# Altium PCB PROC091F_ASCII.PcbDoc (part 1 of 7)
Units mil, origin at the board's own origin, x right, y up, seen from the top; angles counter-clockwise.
Board outline 3590.95 x 906.17 mil, 8 copper layers (Top Layer, GND1, Sig1, PWR1, PWR2, Sig2, GND2, Bottom Layer), stack 63.146 mil thick; 420 components, 316 nets, 1432 pads, 774 vias.
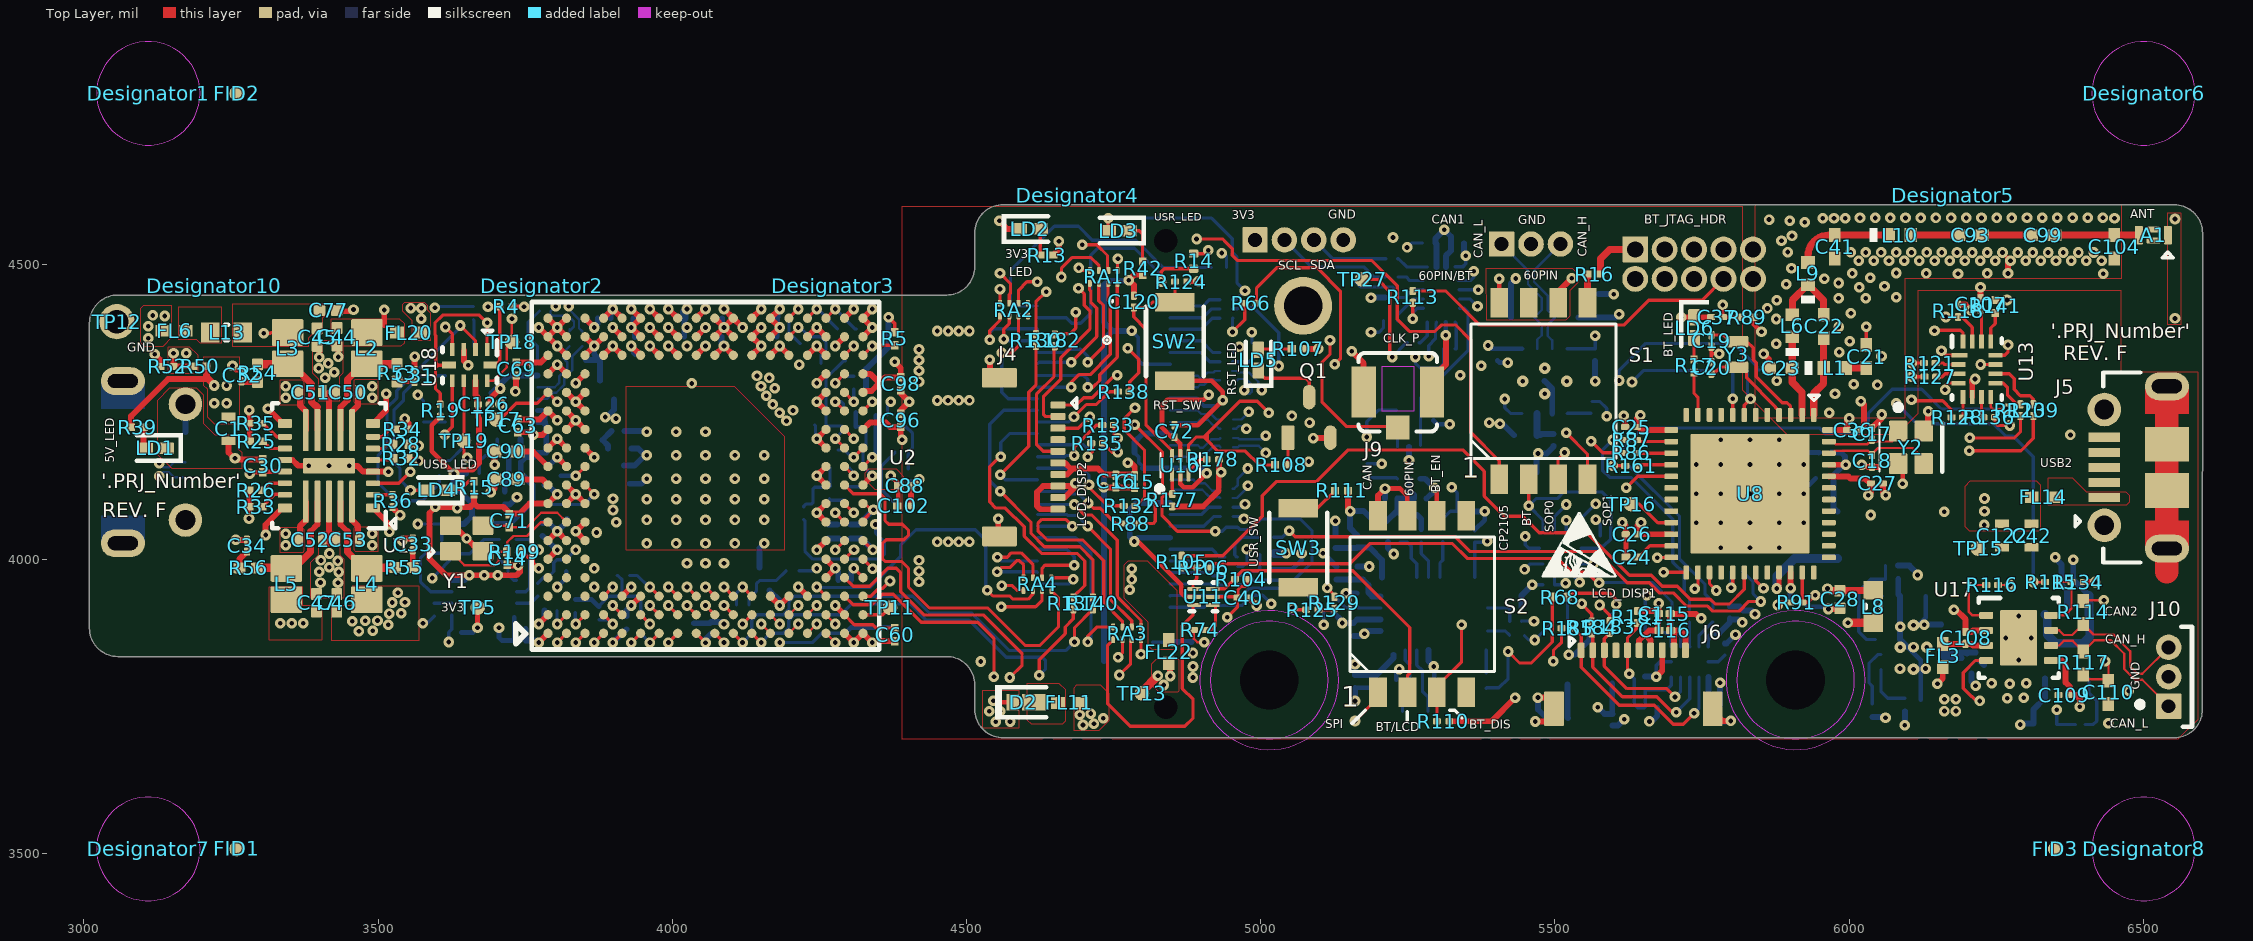
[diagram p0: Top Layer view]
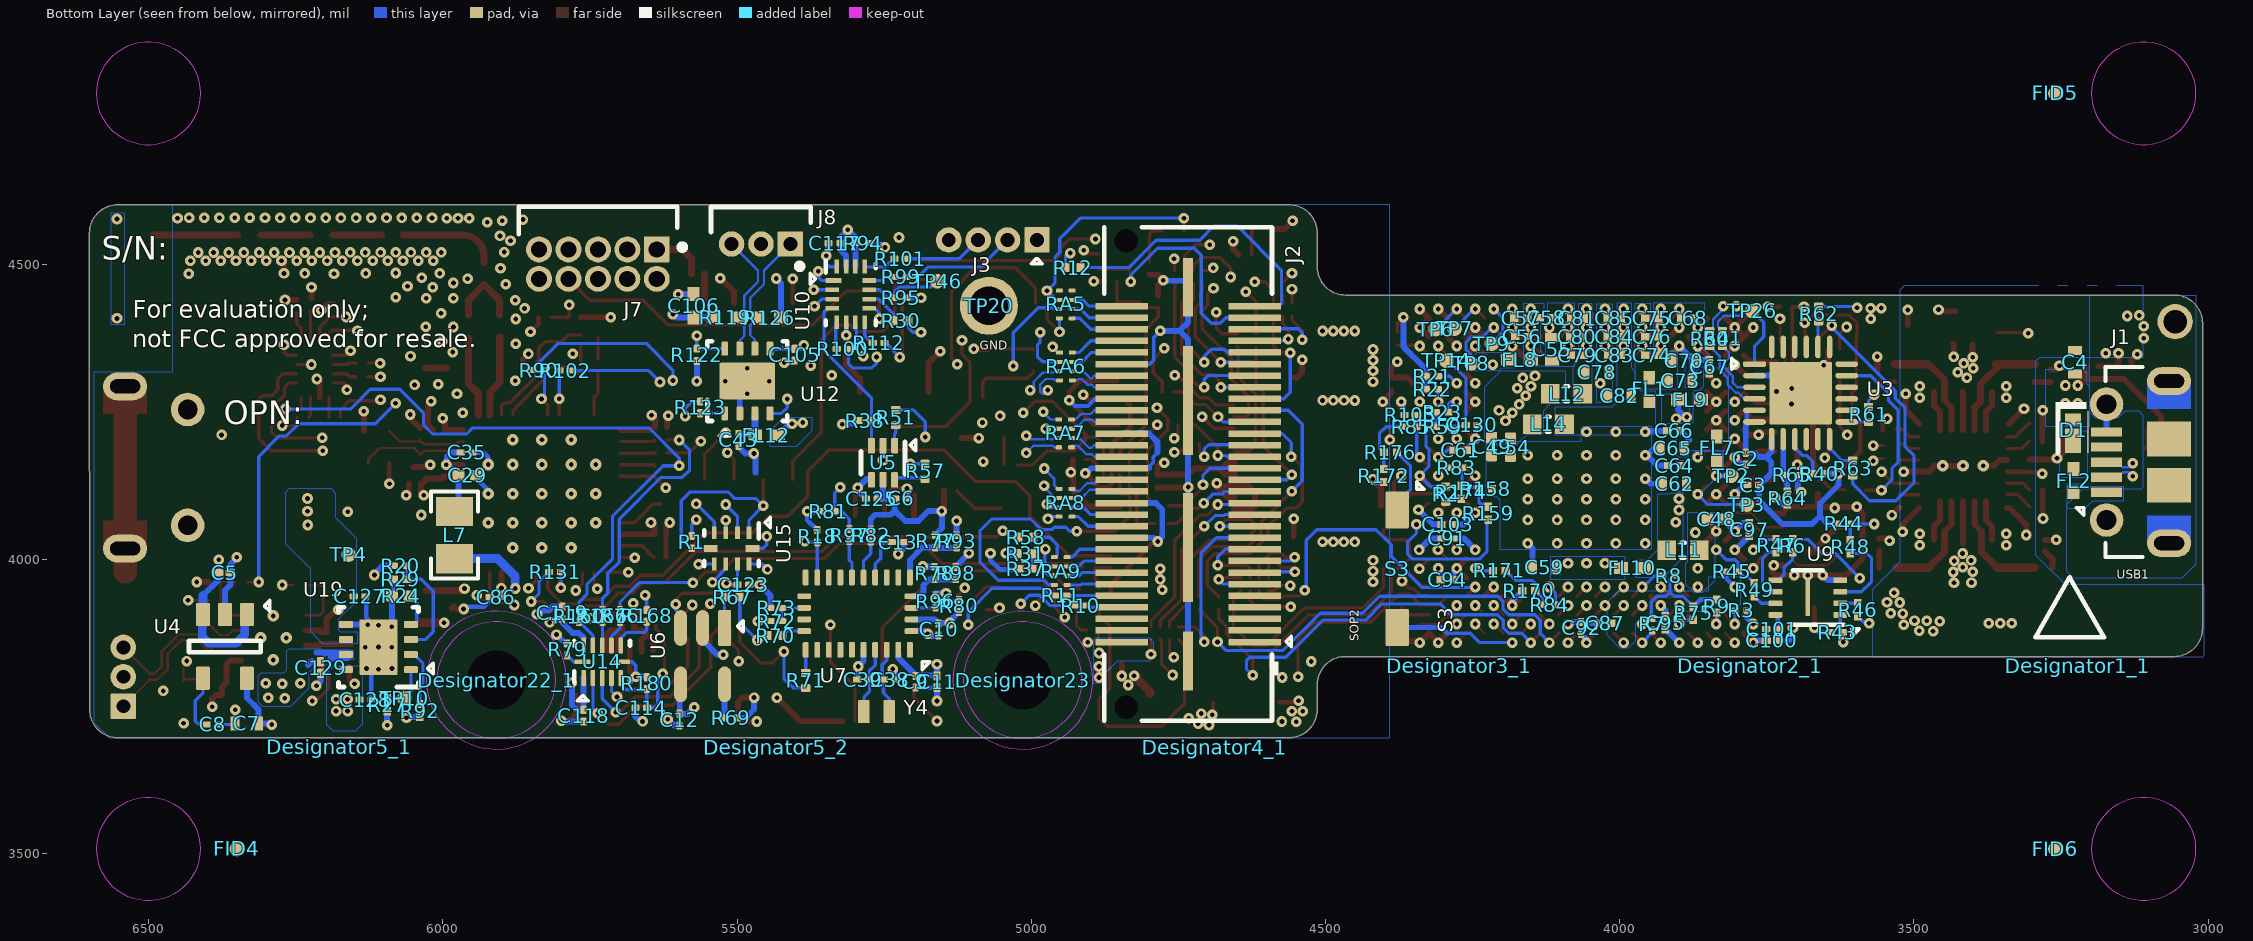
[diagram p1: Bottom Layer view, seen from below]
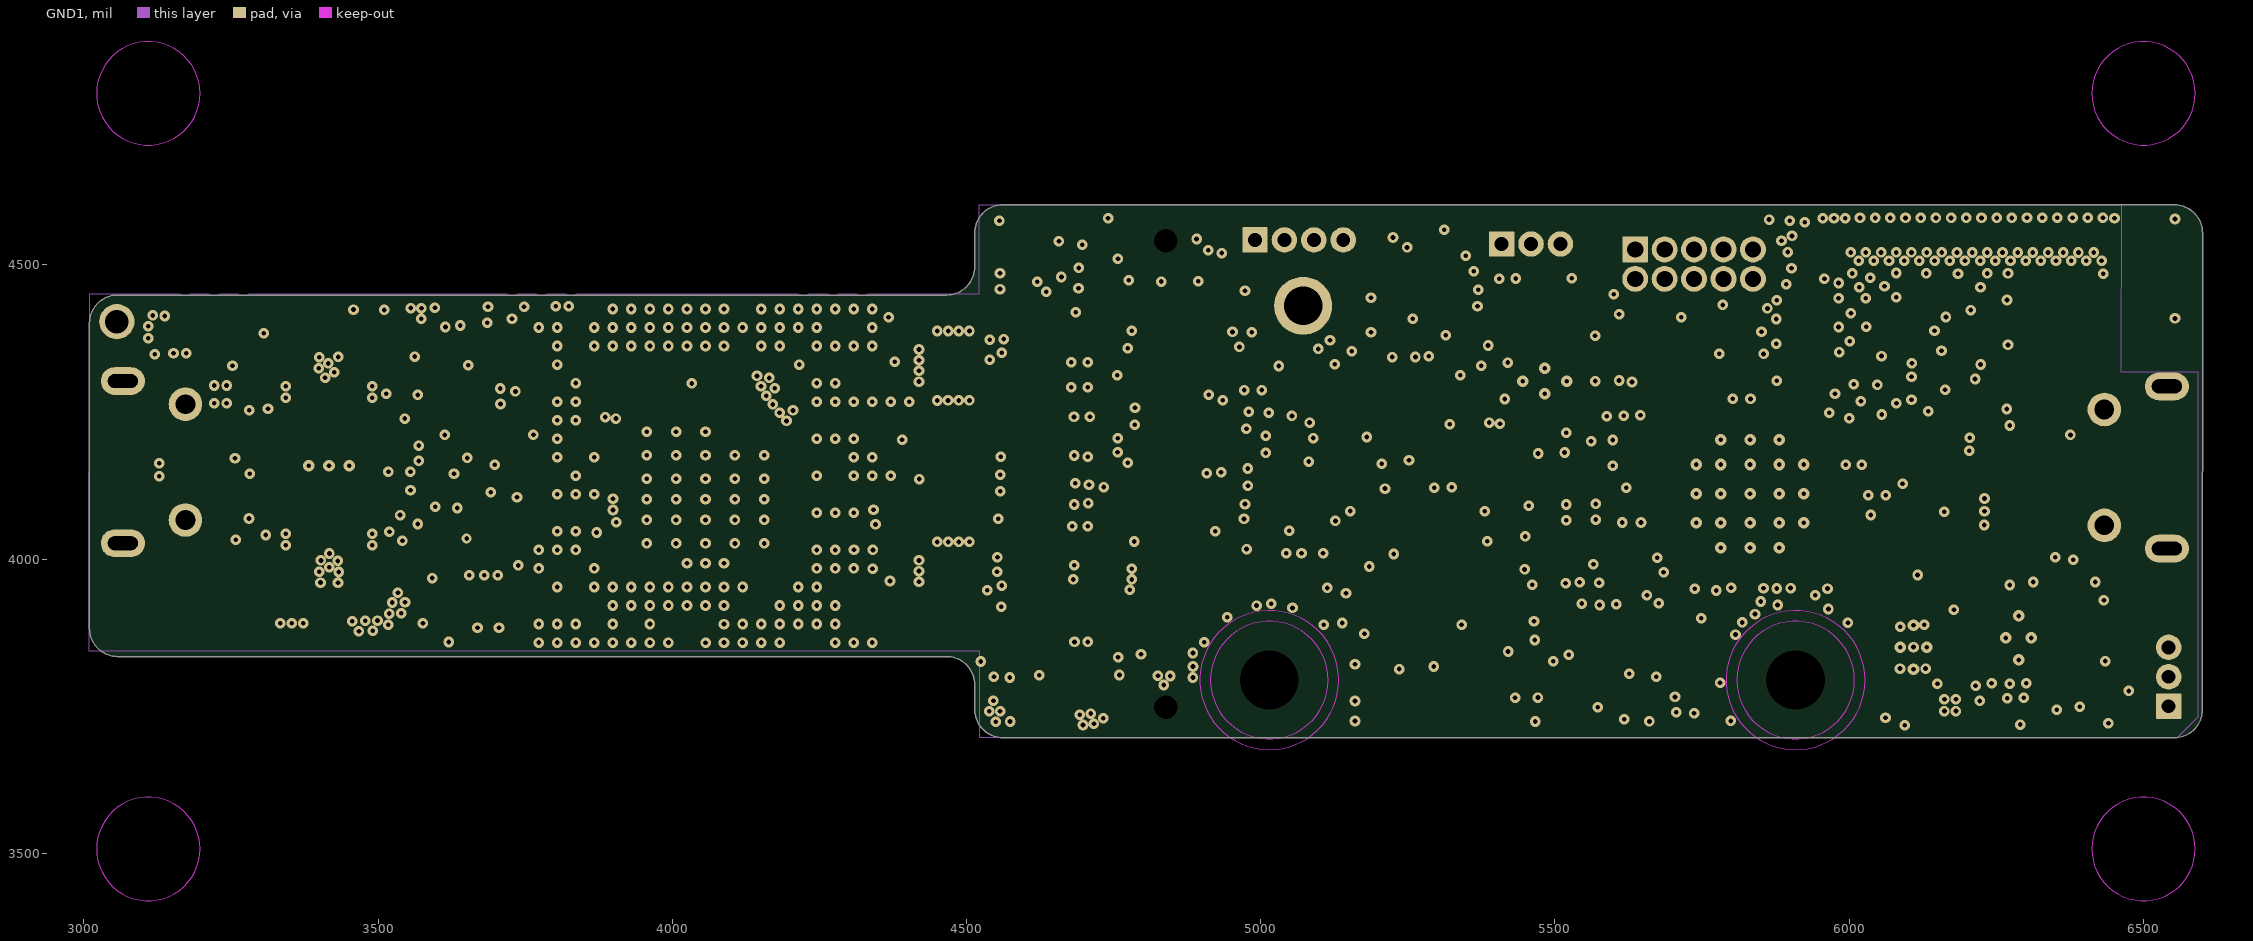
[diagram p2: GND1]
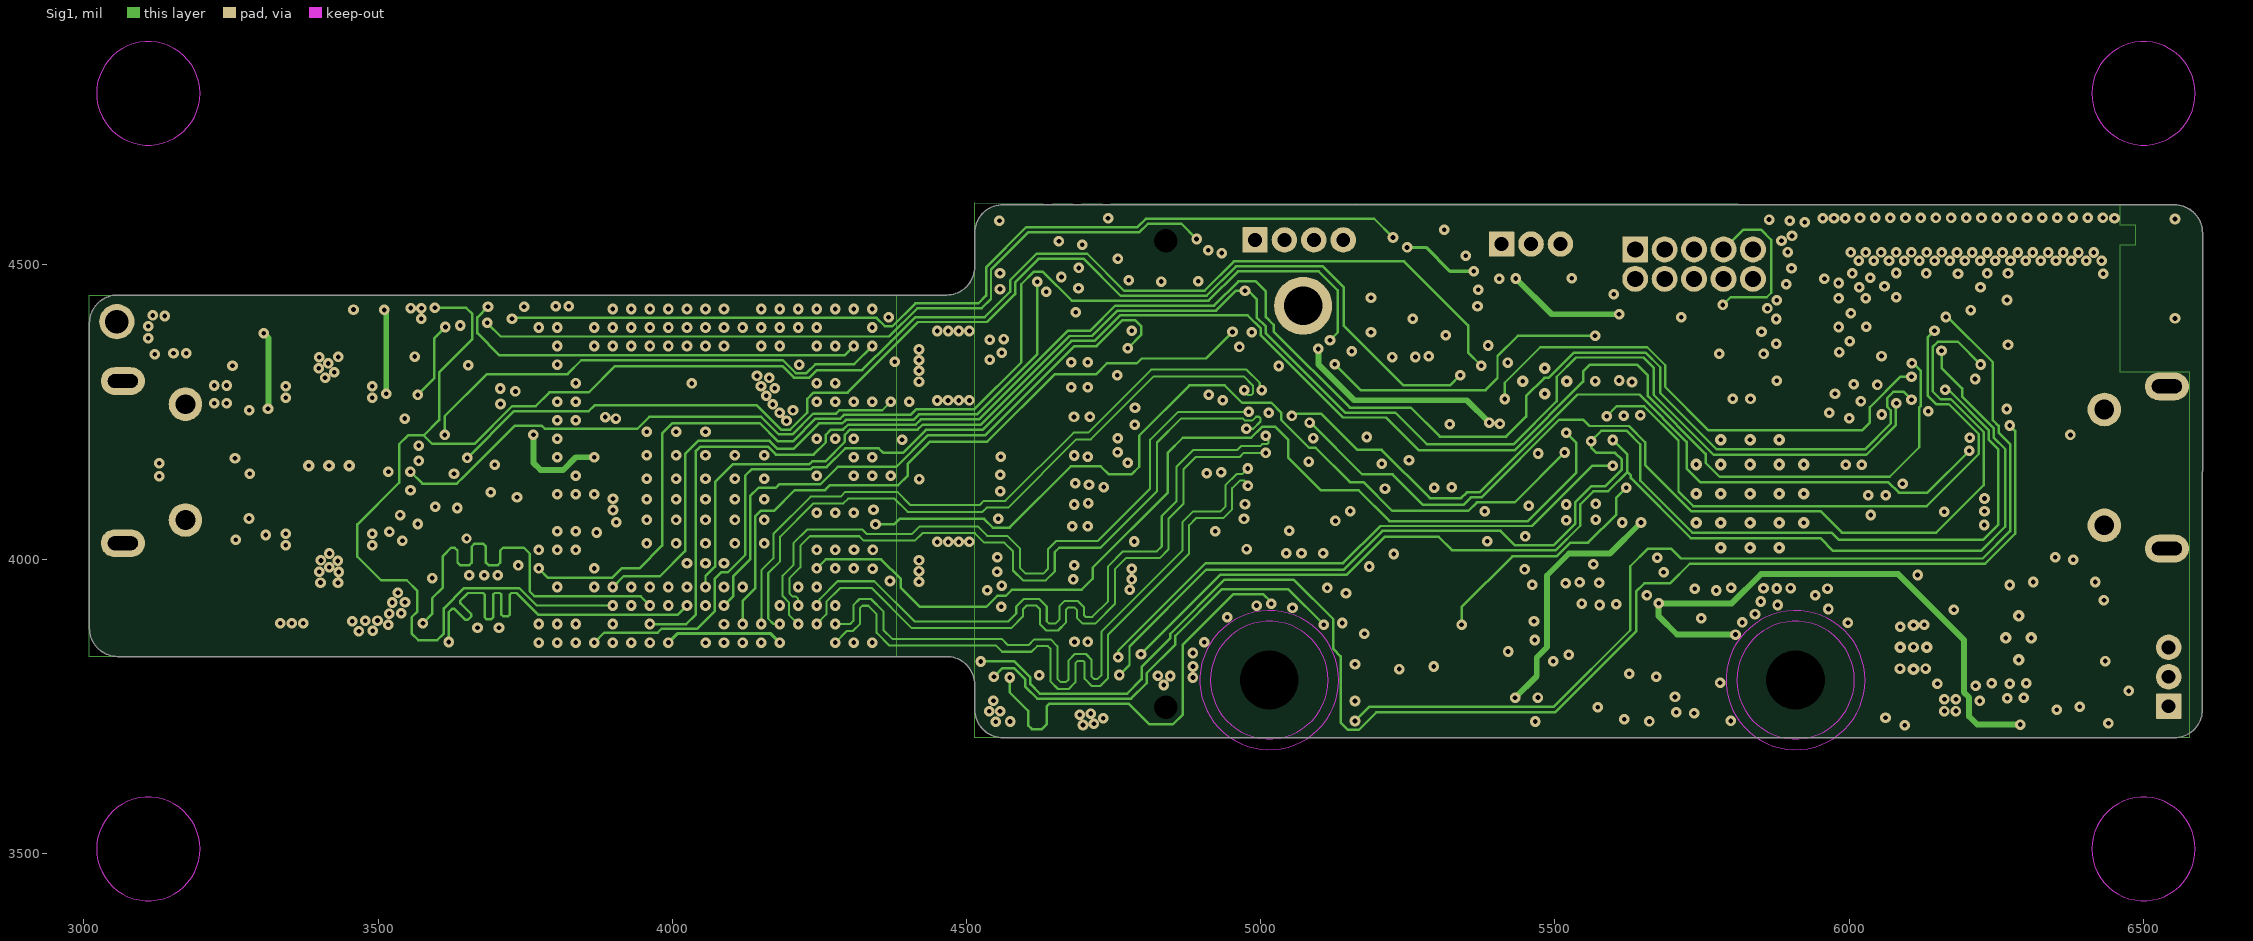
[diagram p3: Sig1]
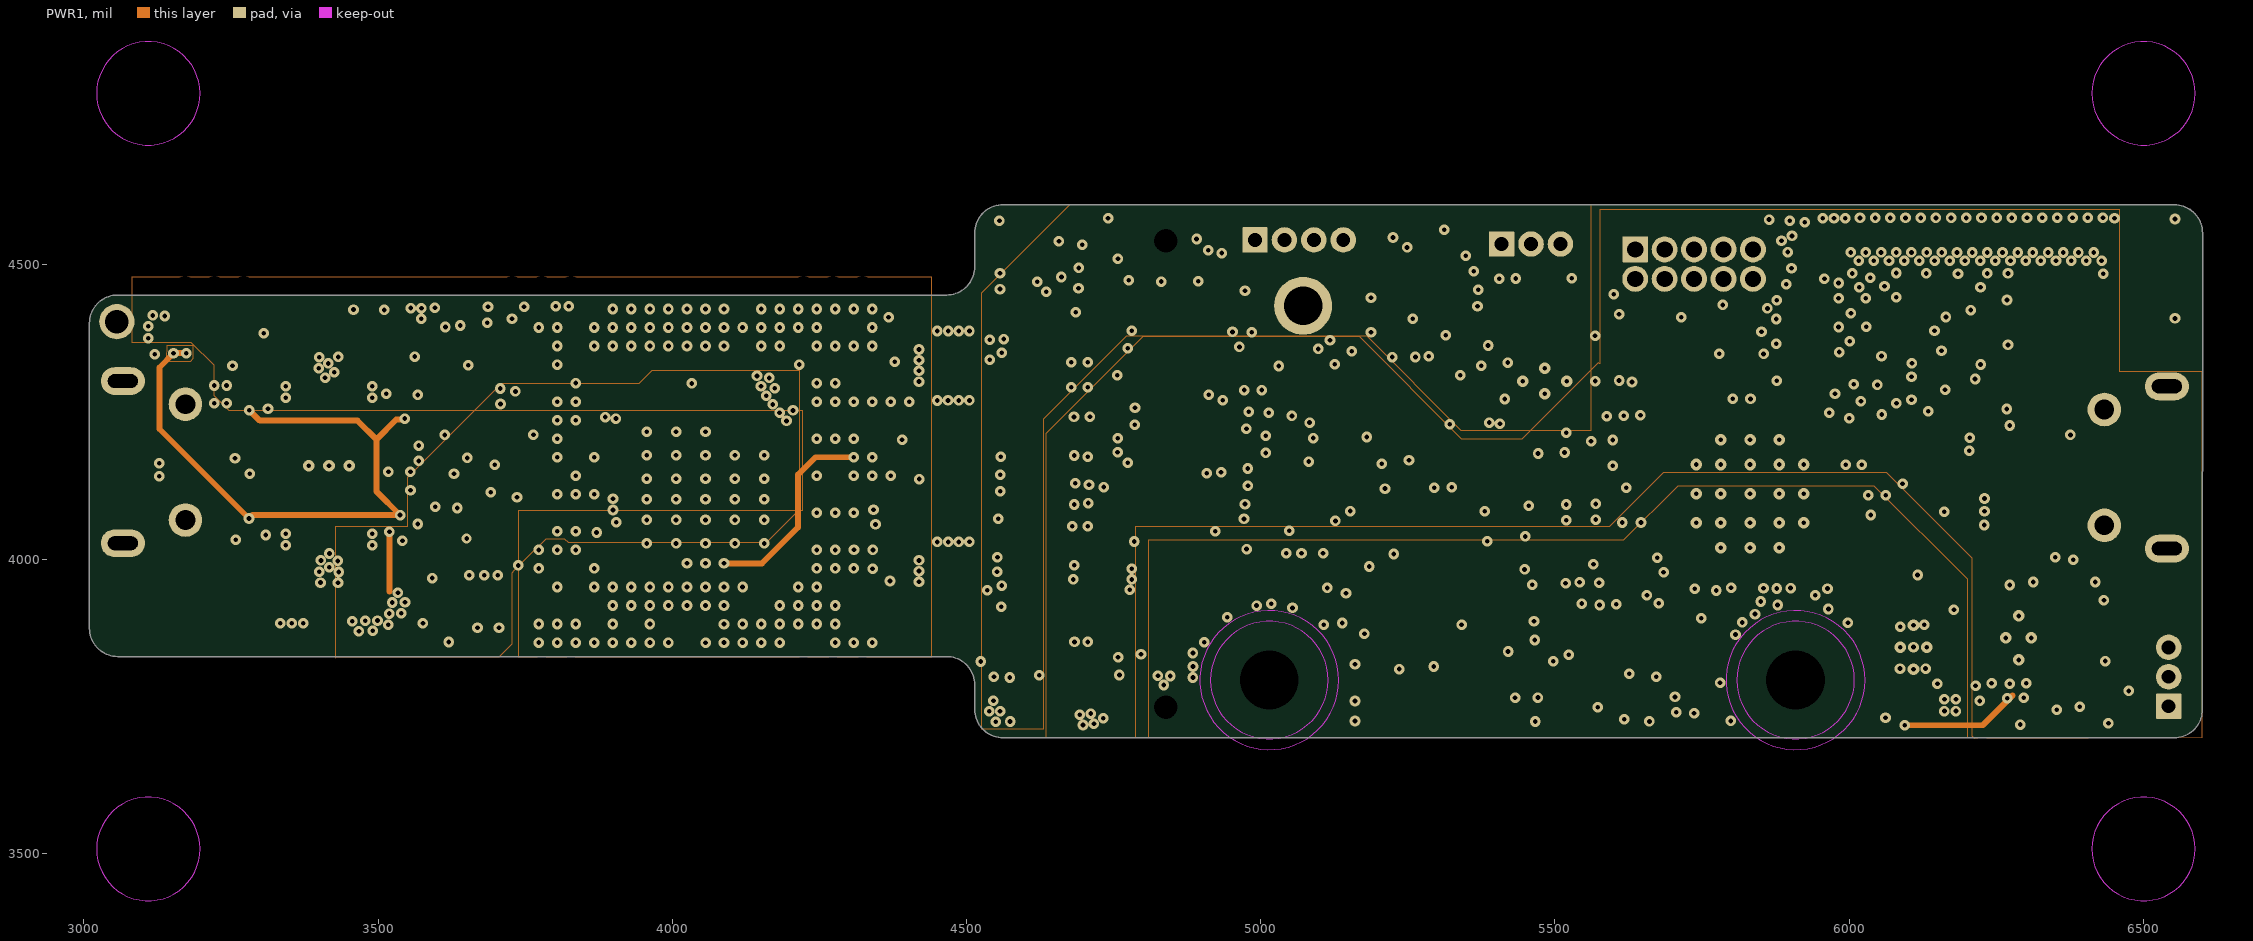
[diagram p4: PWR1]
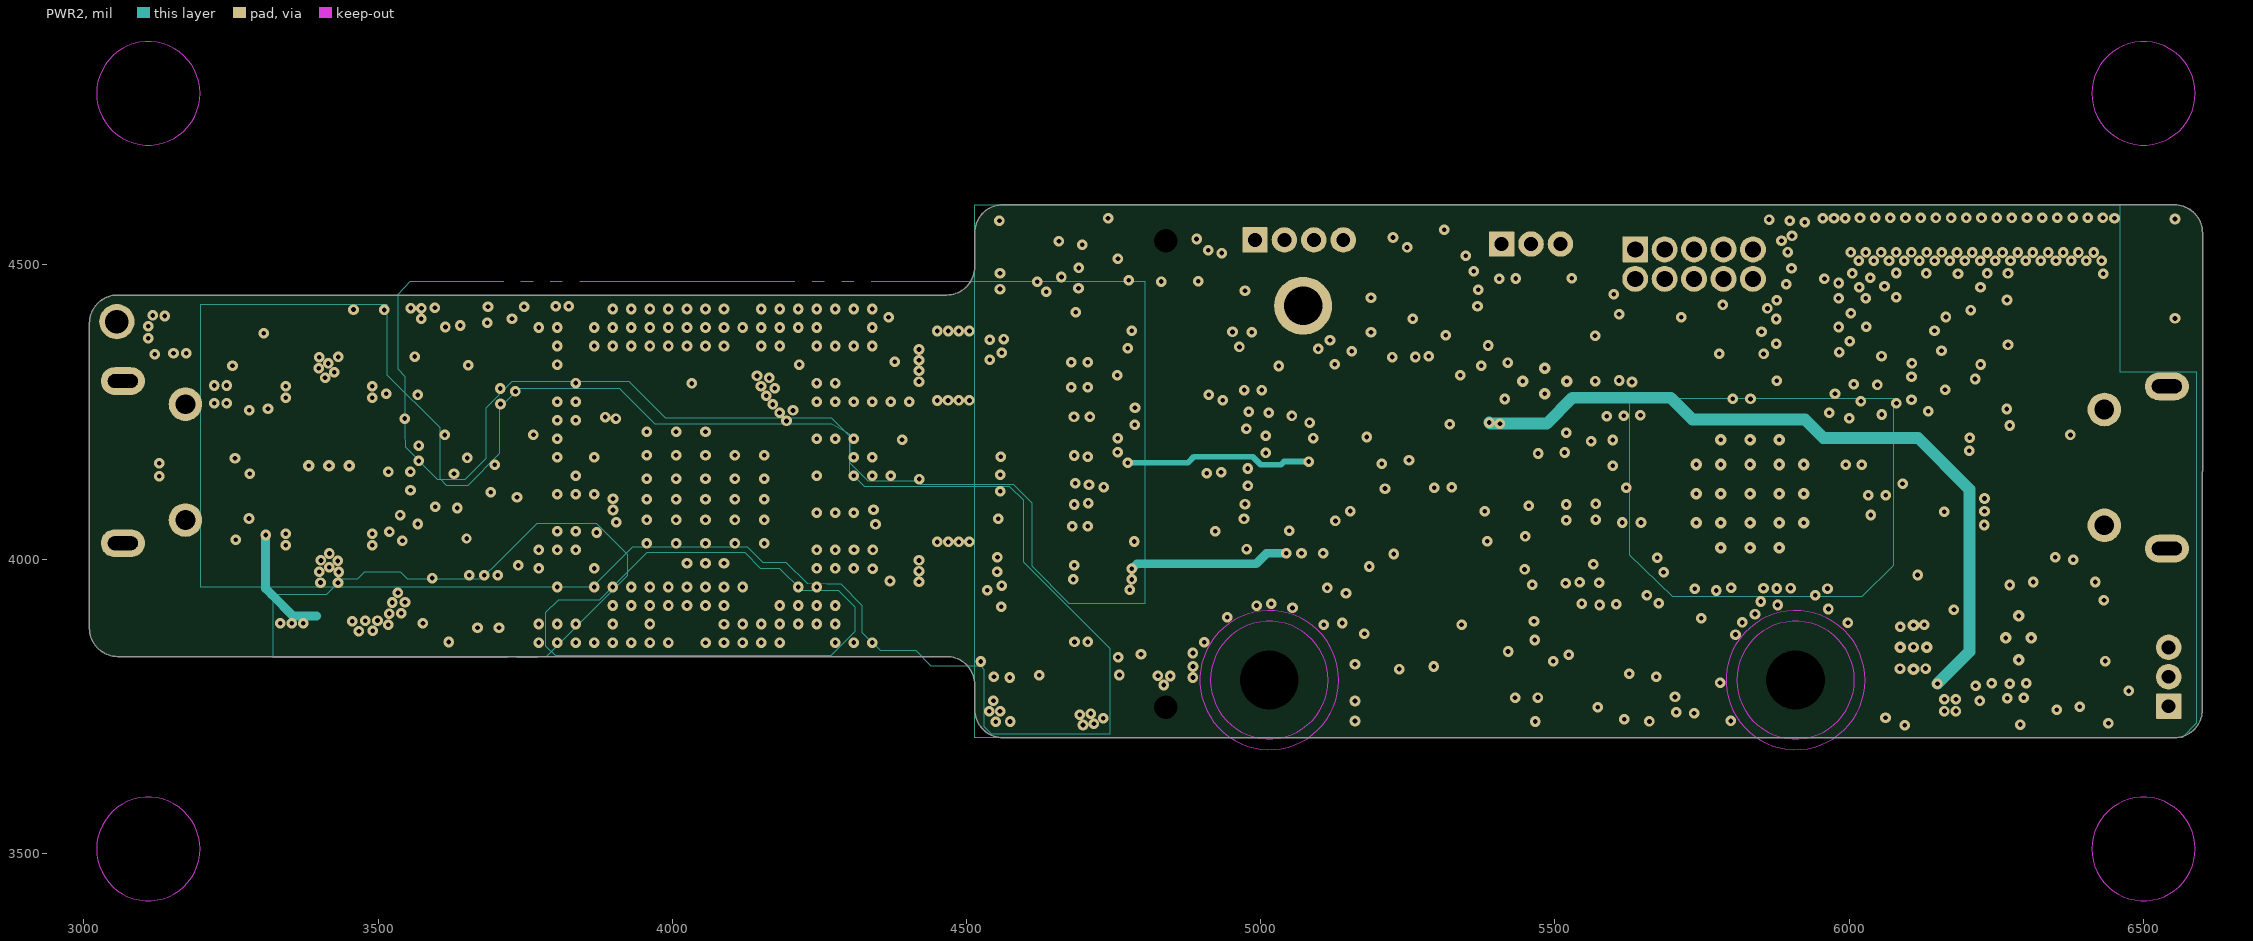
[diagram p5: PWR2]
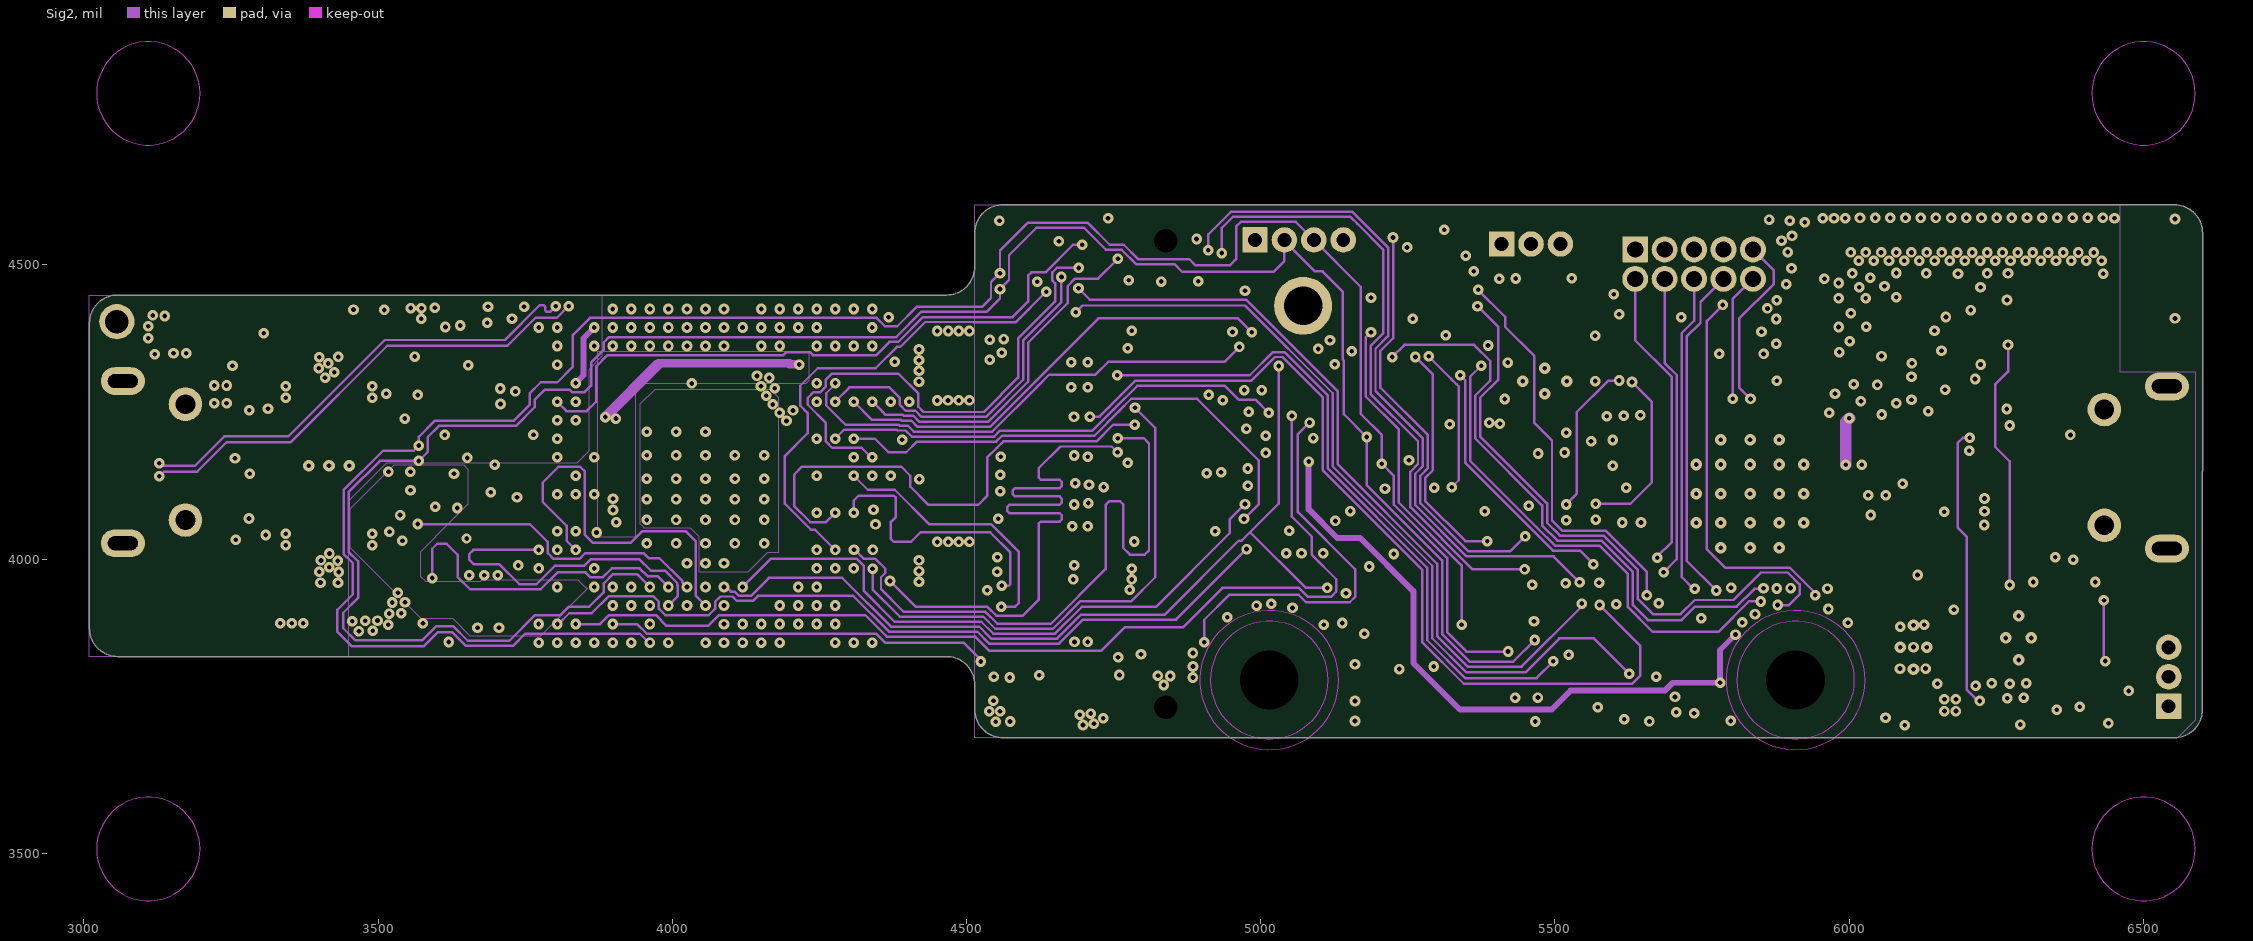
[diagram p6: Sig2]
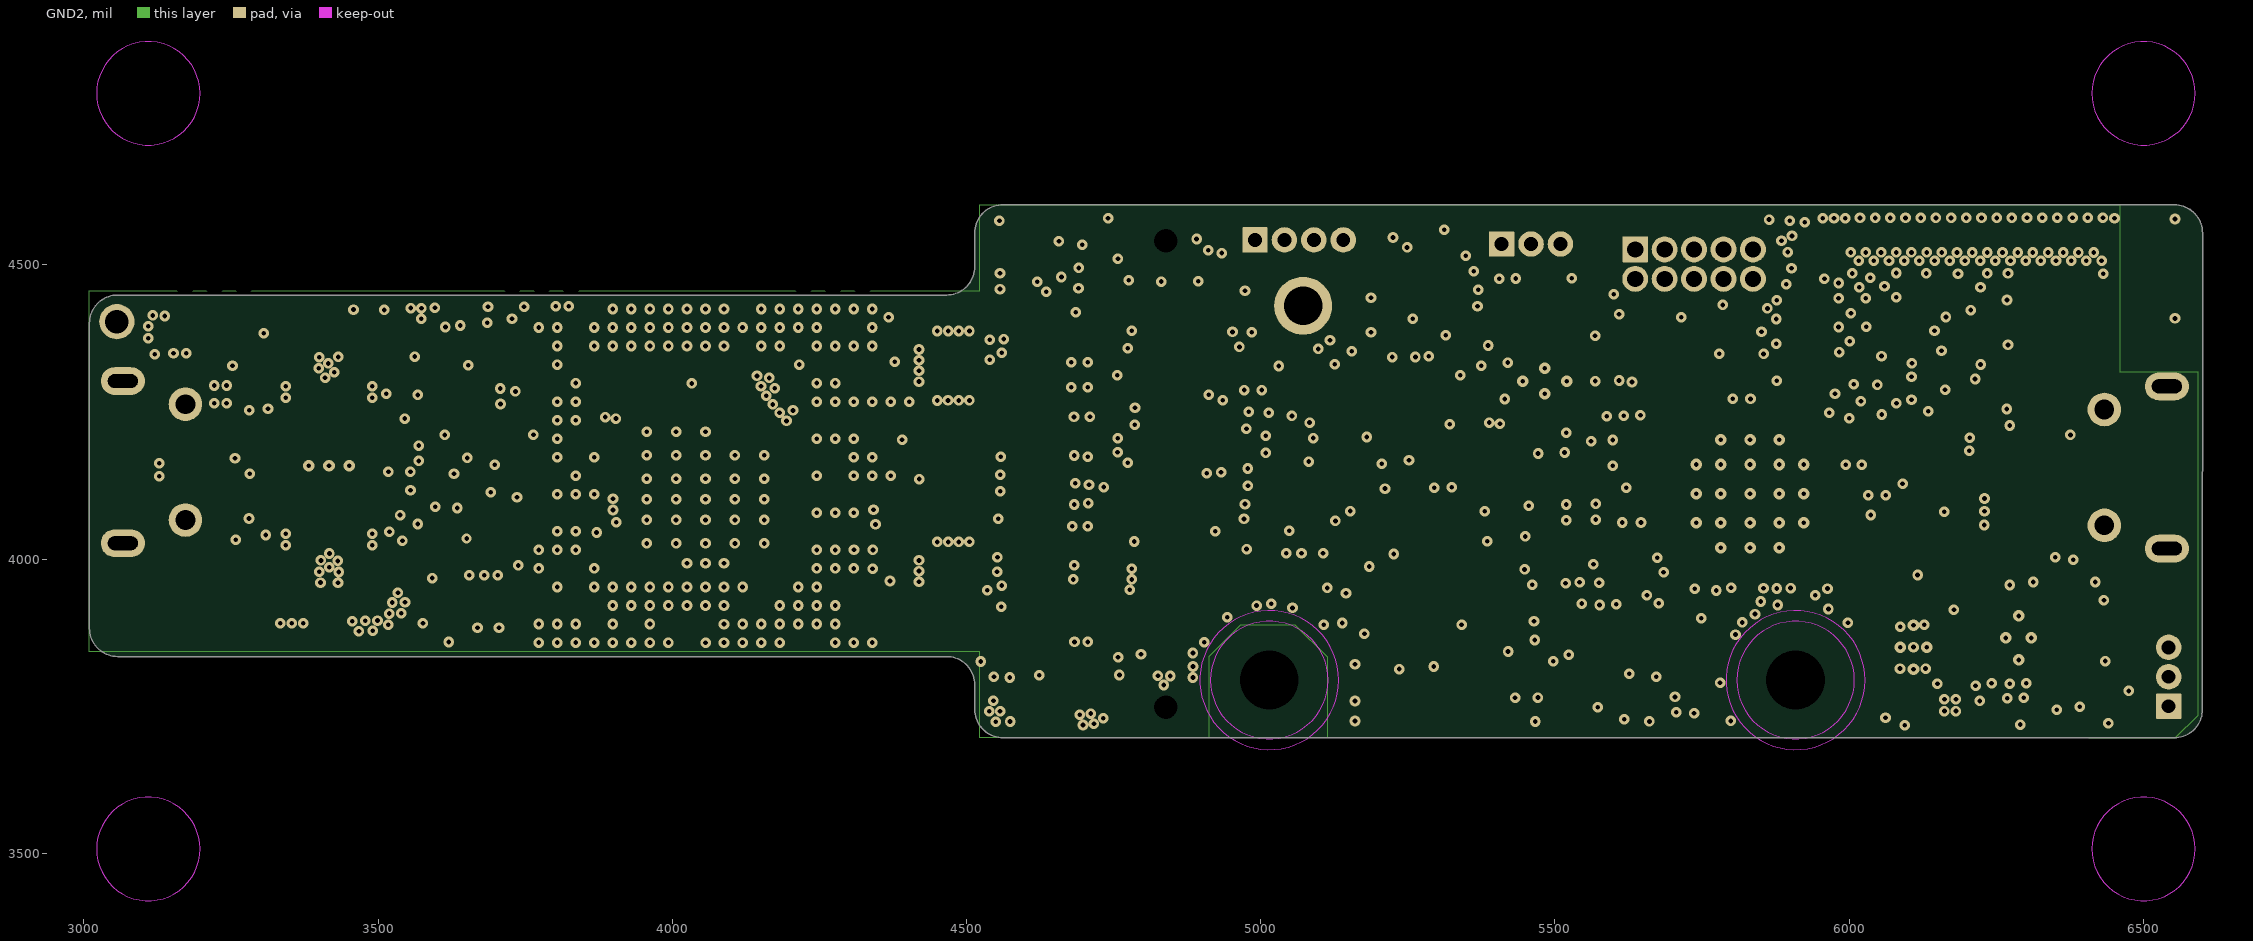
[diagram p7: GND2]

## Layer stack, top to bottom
Top Solder: solder mask 0.5, Solder Resist, Dk 3.5
Top Layer: signal copper 1.373
Dielectric1: core 3.7, FR-4 High Tg, Dk 4.2
GND1: signal copper 2.4
Dielectric3: dielectric 4.5, FR-4 High Tg, Dk 4.2
Sig1: signal copper 1.2
Dielectric2: dielectric 12, FR-4 High Tg, Dk 4.2
PWR1: signal copper 2.4
Dielectric4: dielectric 8, FR-4 High Tg, Dk 4.2
PWR2: signal copper 2.4
Dielectric5: dielectric 12, FR-4 High Tg, Dk 4.2
Sig2: signal copper 1.2
Dielectric8: dielectric 4.5, FR-4 High Tg, Dk 4.2
GND2: signal copper 2.4
Dielectric9: dielectric 3.7, FR-4 High Tg, Dk 4.2
Bottom Layer: signal copper 1.373
Bottom Solder: solder mask 0.5, Solder Resist, Dk 3.5

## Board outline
3057.58,3834.46 4466.14,3834.46 cw(c4466.14,3786.46) 4514.14,3786.46 4514.14,3744.46 ccw(c4562.14,3744.46) 4562.14,3696.46 4562.14,3696.51 6552.27,3696.2 ccw(c6552.27,3744.2) 6600.27,3744.2 6600.29,3744.2 6600.53,4554.1 ccw(c6552.53,4554.1) 6552.53,4602.1 6552.53,4602.08 4562.15,4602.33 4562.15,4602.37 ccw(c4562.15,4554.37) 4514.15,4554.37 4514.15,4496.76 cw(c4466.15,4496.76) 4466.15,4448.76 3057.58,4448.76 ccw(c3057.58,4400.76) 3009.58,4400.76 3009.58,3882.46 ccw(c3057.58,3882.46)

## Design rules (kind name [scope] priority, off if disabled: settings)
AcuteAngle [All] p0: scope1count=1 scope1_0_kind=Board scope1_0_value=Board scope2count=1 scope2_0_kind=Board scope2_0_value=Board commentlength=0 minimum=4.50000000000000E+0001
AcuteAngle [All] p1: minimum=4.50000000000000E+0001 checktracksonly=TRUE
AssemblyTestPointUsage [All] p0: scope1count=1 scope1_0_kind=Board scope1_0_value=Board scope2count=1 scope2_0_kind=Board scope2_0_value=Board commentlength=0
AssemblyTestPointUsage [All] p1: valid=2
AssemblyTestpoint [All] p0: scope1count=1 scope1_0_kind=Board scope1_0_value=Board scope2count=1 scope2_0_kind=Board scope2_0_value=Board commentlength=0
BoardOutlineClearance [All] p0 off: scope1count=1 scope1_0_kind=Board scope1_0_value=Board scope2count=1 scope2_0_kind=Board scope2_0_value=Board commentlength=81 gap=12 // Protel DXP Scope 1 Expression Was: NOT(OnTopSilkscreen OR OnBottomSilkscreen)
BoardOutlineClearance BoardOutlineClearance_1 [All] p0: scope1count=1 scope1_0_kind=Net scope1_0_value=GND scope2count=1 scope2_0_kind=Board scope2_0_value=Board commentlength=0 gap=8
BoardOutlineClearance BoardOutlineClearance_1 [InNet('GND')] p1: gap=8 ignorepadtopadclearanceinfootprint=FALSE
BoardOutlineClearance [NOT(OnTopSilkscreen OR OnBottomSilkscreen)] p2: gap=12 ignorepadtopadclearanceinfootprint=FALSE except(0: Text-OutlineEdge)
Clearance INNERlayer [All] p0 off: scope1count=1 scope1_0_kind=Board scope1_0_value=Board scope2count=1 scope2_0_kind=Board scope2_0_value=Board commentlength=75 gap=8 // Protel DXP Scope 1 Expression Was: (OnLayer('pwr1') or OnLayer('pwr2'))
Clearance "SAME NET" [All] p0: scope1count=1 scope1_0_kind=Board scope1_0_value=Board scope2count=1 scope2_0_kind=Board scope2_0_value=Board commentlength=0 gap=0
Clearance [All] p0: scope1count=1 scope1_0_kind=Board scope1_0_value=Board scope2count=1 scope2_0_kind=Board scope2_0_value=Board commentlength=0 gap=1
Clearance 50E_INNERlayer [All] p0 off: scope1count=1 scope1_0_kind=Board scope1_0_value=Board scope2count=1 scope2_0_kind=Board scope2_0_value=Board commentlength=75 gap=4.2 // Protel DXP Scope 1 Expression Was: (OnLayer('sig1') or OnLayer('Sig2'))
Clearance 100E [All] p0 off: scope1count=1 scope1_0_kind=Board scope1_0_value=Board scope2count=1 scope2_0_kind=Board scope2_0_value=Board commentlength=70 gap=8 // Protel DXP Scope 1 Expression Was: InDifferentialPairClass('100E')
Clearance AOP_Sig [All] p0 off: scope1count=1 scope1_0_kind=Board scope1_0_value=Board scope2count=1 scope2_0_kind=Board scope2_0_value=Board commentlength=97 gap=4 // Protel DXP Scope 1 Expression Was: WithinRoom('BGA') AND (OnLayer('sig1') or OnLayer('sig2'))
Clearance AOP_T-B [All] p0 off: scope1count=1 scope1_0_kind=Board scope1_0_value=Board scope2count=1 scope2_0_kind=Board scope2_0_value=Board commentlength=48 gap=4 // Protel DXP Scope 2 Expression Was: OnOutside
Clearance 90E_OUTSIDE [All] p0 off: scope1count=1 scope1_0_kind=Board scope1_0_value=Board scope2count=1 scope2_0_kind=Board scope2_0_value=Board commentlength=48 gap=6 // Protel DXP Scope 2 Expression Was: OnOutside
Clearance RF_TRACE [All] p0: scope1count=1 scope1_0_kind=NetClass scope1_0_value=RF scope2count=1 scope2_0_kind=Board scope2_0_value=Board commentlength=0 gap=4
Clearance Keepout [All] p0 off: scope1count=1 scope1_0_kind=Board scope1_0_value=Board scope2count=1 scope2_0_kind=Board scope2_0_value=Board commentlength=66 gap=0.01 // Protel DXP Scope 1 Expression Was: (OnLayer('Keep-Out Layer'))
Clearance Keepout [(OnLayer('Keep-Out Layer'))] p1: gap=0.01 ignorepadtopadclearanceinfootprint=FALSE except(5.9: THPad-THPad; 7: Arc-THPad Track-THPad THPad-Via; 8: THPad-Fill THPad-Poly THPad-Region)
Clearance RF_TRACE [InNetClass('RF')] p2: gap=4 ignorepadtopadclearanceinfootprint=FALSE except(0: Arc-Hole Track-Hole SMDPad-Hole THPad-Hole Via-Hole Fill-Hole Poly-Hole Region-Hole Text-Hole; 2: Arc-Text Track-Text SMDPad-Text THPad-Text Via-Text Fill-Text Poly-Text Region-Text Text-Text; 5.9: THPad-THPad; 6: SMDPad-Fill SMDPad-Poly SMDPad-Region Via-Fill Via-Poly Via-Region; 7: Arc-THPad Track-THPad THPad-Via; 8: THPad-Fill THPad-Poly THPad-Region; 10: Arc-Fill Arc-Poly Arc-Region Track-Fill Track-Poly Track-Region; 15: Fill-Fill Fill-Poly Fill-Region Poly-Poly Poly-Region Region-Region)
Clearance AOP_T-B [WithinRoom('BGA') vs OnOutside] p3: gap=4 ignorepadtopadclearanceinfootprint=TRUE except(0: Arc-Hole Track-Hole SMDPad-Hole THPad-Hole Via-Hole Fill-Hole Poly-Hole Region-Hole Text-Hole; 3.8: SMDPad-Via; 3.9: Arc-Via Track-Via; 5.9: THPad-THPad; 7: Arc-THPad Track-THPad THPad-Via; 8: THPad-Fill THPad-Poly THPad-Region Fill-Fill Fill-Poly Fill-Region Poly-Poly Poly-Region Region-Region)
Clearance AOP_Sig [WithinRoom('BGA') AND (OnLayer('sig1') or OnLayer('sig2'))] p4: gap=4 ignorepadtopadclearanceinfootprint=FALSE except(0: Arc-Hole Track-Hole SMDPad-Hole THPad-Hole Via-Hole Fill-Hole Poly-Hole Region-Hole Text-Hole; 3.5: Arc-Arc Arc-Track Arc-Via Arc-Text Track-Track Track-Via Track-Text SMDPad-Text THPad-Text Via-Via Via-Text Fill-Text Poly-Text Region-Text Text-Text; 3.8: SMDPad-Via; 5.9: THPad-THPad; 7: Arc-THPad Track-THPad THPad-Via; 8: SMDPad-THPad THPad-Fill THPad-Poly THPad-Region; 15: Fill-Fill Fill-Poly Fill-Region Poly-Poly Poly-Region Region-Region)
Clearance 50E_INNERlayer [(OnLayer('sig1') or OnLayer('Sig2'))] p5: gap=4.2 ignorepadtopadclearanceinfootprint=TRUE except(0: Arc-Hole Track-Hole SMDPad-Hole THPad-Hole Via-Hole Fill-Hole Poly-Hole Region-Hole Text-Hole; 2: SMDPad-Text Fill-Text Poly-Text Region-Text Text-Text; 5.9: THPad-THPad; 6: SMDPad-Fill SMDPad-Poly SMDPad-Region; 7: Arc-THPad Track-THPad THPad-Via; 8: Arc-Fill Arc-Poly Arc-Region Track-Fill Track-Poly Track-Region THPad-Fill THPad-Poly THPad-Region; 12: Fill-Fill Fill-Poly Fill-Region Poly-Poly Poly-Region Region-Region)
Clearance INNERlayer [(OnLayer('pwr1') or OnLayer('pwr2'))] p6: gap=8 ignorepadtopadclearanceinfootprint=TRUE except(0: Arc-Hole Track-Hole SMDPad-Hole THPad-Hole Via-Hole Fill-Hole Poly-Hole Region-Hole Text-Hole; 2: SMDPad-Text Fill-Text Poly-Text Region-Text Text-Text; 4: Via-Fill Via-Poly Via-Region; 4.2: Arc-Text Track-Text THPad-Text Via-Via Via-Text; 5: THPad-Fill THPad-Poly THPad-Region; 5.9: THPad-THPad; 6: Arc-Via Arc-Fill Arc-Poly Arc-Region Track-Via Track-Fill Track-Poly Track-Region; 7: THPad-Via; 12: Fill-Fill Fill-Poly Fill-Region Poly-Poly Poly-Region Region-Region)
Clearance 100E [InDifferentialPairClass('100E')] p7: gap=8 ignorepadtopadclearanceinfootprint=FALSE except(0: Arc-Hole Track-Hole SMDPad-Hole THPad-Hole Via-Hole Fill-Hole Poly-Hole Region-Hole Text-Hole; 2: Arc-Text Track-Text THPad-Text Via-Text Fill-Text Poly-Text Region-Text Text-Text; 4: Arc-SMDPad Track-SMDPad SMDPad-SMDPad SMDPad-THPad SMDPad-Via SMDPad-Text Via-Via Via-Fill Via-Poly Via-Region; 5: Arc-Via Track-Via; 5.9: THPad-THPad; 6: SMDPad-Fill SMDPad-Poly SMDPad-Region Fill-Fill Fill-Poly Fill-Region Poly-Poly Poly-Region Region-Region; 7: Arc-THPad Track-THPad THPad-Via)
Clearance 90E_OUTSIDE [InDifferentialPairClass('90E') vs OnOutside] p8: gap=6 ignorepadtopadclearanceinfootprint=TRUE except(0: Arc-Hole Track-Hole SMDPad-Hole THPad-Hole Via-Hole Fill-Fill Fill-Poly Fill-Region Fill-Hole Poly-Poly Poly-Region Poly-Hole Region-Region Region-Hole Text-Hole; 2: Arc-Text Track-Text SMDPad-Text THPad-Text Via-Text Fill-Text Poly-Text Region-Text Text-Text; 3.8: SMDPad-Via; 4: Arc-SMDPad Track-SMDPad SMDPad-SMDPad Via-Via Via-Fill Via-Poly Via-Region; 4.5: Arc-Arc Arc-Track Arc-Via Track-Track Track-Via; 5.9: THPad-THPad; 7: Arc-THPad Track-THPad SMDPad-THPad THPad-Via; 8: THPad-Fill THPad-Poly THPad-Region)
Clearance [All] p9: gap=1 ignorepadtopadclearanceinfootprint=TRUE except(0: Arc-Hole Track-Hole SMDPad-Hole THPad-Hole Via-Hole Fill-Hole Poly-Hole Region-Hole Text-Hole; 4: SMDPad-SMDPad SMDPad-Via Via-Via Via-Fill Via-Poly Via-Region; 5: Arc-SMDPad Arc-Fill Arc-Poly Arc-Region Track-SMDPad Track-Fill Track-Poly Track-Region; 5.9: THPad-THPad; 6: Arc-Arc Arc-Track Arc-Via Track-Track Track-Via SMDPad-Fill SMDPad-Poly SMDPad-Region; 7: Arc-THPad Track-THPad SMDPad-THPad THPad-Via; 8: THPad-Fill THPad-Poly THPad-Region; 12: Fill-Fill Fill-Poly Fill-Region Poly-Poly Poly-Region Region-Region)
Clearance "SAME NET" [All] p10: gap=0 ignorepadtopadclearanceinfootprint=FALSE except(0.5: SMDPad-Text; 5.9: THPad-THPad)
ComponentClearance ComponentClearance_THtoTH [All] p0 off: scope1count=1 scope1_0_kind=Board scope1_0_value=Board scope2count=1 scope2_0_kind=Board scope2_0_value=Board commentlength=54 gap=20 collisioncheckmode=3 // Protel DXP Scope 2 Expression Was: IsThruComponent
ComponentClearance ComponentClearance_THtoSMT [All] p0 off: scope1count=1 scope1_0_kind=Board scope1_0_value=Board scope2count=1 scope2_0_kind=Board scope2_0_value=Board commentlength=53 gap=5 collisioncheckmode=3 // Protel DXP Scope 2 Expression Was: IsSMTComponent
ComponentClearance ComponentClearance_SmallPassives [All] p0 off: scope1count=1 scope1_0_kind=Board scope1_0_value=Board scope2count=1 scope2_0_kind=Board scope2_0_value=Board commentlength=508 gap=10 collisioncheckmode=3 // Protel DXP Scope 2 Expression Was: HasFootprint('0201*') or HasFootprint('0402*') or HasFootprint('0508') or HasFootprint('0603*') or HasFootprint('0612') or HasFootprint('0805*') or HasFootprint('0815*') or HasFootprint('0830*') or HasFootprint('1206*') or HasFootprint('1210*') or HasFootprint('1808*') or HasFootprint('1812*') or HasFootprint('1825*') or HasFootprint('2010*') or HasFootprint('2220*') or HasFootprint('2225*') or HasFootprint('2512*') or HasFootprint('2728*') or HasFootprint('3518*')
ComponentClearance ComponentClearance_MountingHoles [All] p0: scope1count=1 scope1_0_kind=ComponentClass scope1_0_value="Mounting Holes" scope2count=1 scope2_0_kind=Board scope2_0_value=Board commentlength=0 gap=20 collisioncheckmode=3
ComponentClearance ComponentClearance_ScrewToNut [All] p0 off: scope1count=1 scope1_0_kind=Board scope1_0_value=Board scope2count=1 scope2_0_kind=Board scope2_0_value=Board commentlength=71 gap=5 collisioncheckmode=3 // Protel DXP Scope 2 Expression Was: (HasFootprint('Keystone_1902C'))
ComponentClearance ComponentClearance_Logo [All] p0: scope1count=1 scope1_0_kind=ComponentClass scope1_0_value=Logo scope2count=1 scope2_0_kind=Board scope2_0_value=Board commentlength=0 gap=50 collisioncheckmode=3
ComponentClearance ComponentClearance_Shunt [All] p0: scope1count=1 scope1_0_kind=ComponentClass scope1_0_value=Header scope2count=1 scope2_0_kind=ComponentClass scope2_0_value=Shunt commentlength=0 gap=1 collisioncheckmode=3
ComponentClearance ComponentClearance_MountingHoles_FiducialMarks [All] p0: scope1count=1 scope1_0_kind=ComponentClass scope1_0_value="Mounting Holes" scope2count=1 scope2_0_kind=ComponentClass scope2_0_value=FiducialMark commentlength=0 gap=50 collisioncheckmode=3
ComponentClearance [All] p0: scope1count=1 scope1_0_kind=Board scope1_0_value=Board scope2count=1 scope2_0_kind=Board scope2_0_value=Board commentlength=0 gap=1 collisioncheckmode=3
ComponentClearance ComponentClearance_R188_204 [All] p0: scope1count=1 scope1_0_kind=Component scope1_0_value=R188 scope2count=1 scope2_0_kind=Component scope2_0_value=R204 commentlength=0 gap=-1 collisioncheckmode=3
ComponentClearance ComponentClearance_R199_187 [All] p0: scope1count=1 scope1_0_kind=Component scope1_0_value=R199 scope2count=1 scope2_0_kind=Component scope2_0_value=R187 commentlength=0 gap=-1 collisioncheckmode=3
ComponentClearance ComponentClearance_R199_187 [InComponent('R199') vs InComponent('R187')] p1: gap=-1 collisioncheckmode=3 verticalgap=10 showdistances=FALSE
ComponentClearance ComponentClearance_R188_204 [InComponent('R188') vs InComponent('R204')] p2: gap=-1 collisioncheckmode=3 verticalgap=10 showdistances=FALSE
ComponentClearance [All] p3: gap=1 collisioncheckmode=3 verticalgap=10 showdistances=FALSE
ComponentClearance ComponentClearance_MountingHoles_FiducialMarks [InComponentClass('Mounting Holes') vs InComponentClass('FiducialMark')] p4: gap=50 collisioncheckmode=3 verticalgap=10 showdistances=FALSE
ComponentClearance ComponentClearance_Shunt [InComponentClass('Header') vs InComponentClass('Shunt')] p5: gap=1 collisioncheckmode=3 verticalgap=0 showdistances=FALSE
ComponentClearance ComponentClearance_Logo [InComponentClass('Logo')] p6: gap=50 collisioncheckmode=3 verticalgap=10 showdistances=FALSE
ComponentClearance ComponentClearance_ScrewToNut [(HasFootprint('NY PMS 440 0025 PH')) vs (HasFootprint('Keystone_1902C'))] p7: gap=5 collisioncheckmode=3 verticalgap=10 showdistances=FALSE
ComponentClearance ComponentClearance_MountingHoles [InComponentClass('Mounting Holes')] p8: gap=20 collisioncheckmode=3 verticalgap=100000 showdistances=FALSE
ComponentClearance ComponentClearance_SmallPassives [HasFootprint('0201*') or HasFootprint('0402*') or HasFootprint('0508') or HasFootprint('0603*') or HasFootprint('0612') or HasFootprint('0805*') or HasFootprint('0815*') or HasFootprint('0830*') or HasFootprint('1206*') or HasFootprint('1210*') or HasFootprint('1808*') or HasFootprint('1812*') or HasFootprint('1825*') or HasFootprint('2010*') or HasFootprint('2220*') or HasFootprint('2225*') or HasFootprint('2512*') or HasFootprint('2728*') or HasFootprint('3518*') vs HasFootprint('0201*') or HasFootprint('0402*') or HasFootprint('0508') or HasFootprint('0603*') or HasFootprint('0612') or HasFootprint('0805*') or HasFootprint('0815*') or HasFootprint('0830*') or HasFootprint('1206*') or HasFootprint('1210*') or HasFootprint('1808*') or HasFootprint('1812*') or HasFootprint('1825*') or HasFootprint('2010*') or HasFootprint('2220*') or HasFootprint('2225*') or HasFootprint('2512*') or HasFootprint('2728*') or HasFootprint('3518*')] p9: gap=10 collisioncheckmode=3 verticalgap=10 showdistances=FALSE
ComponentClearance ComponentClearance_THtoSMT [IsThruComponent vs IsSMTComponent] p10: gap=5 collisioncheckmode=3 verticalgap=20 showdistances=FALSE
ComponentClearance ComponentClearance_THtoTH [IsThruComponent vs IsThruComponent] p11: gap=20 collisioncheckmode=3 verticalgap=30 showdistances=FALSE
DiffPairsRouting Diff_120E [All] p0: scope1count=1 scope1_0_kind=Board scope1_0_value=Board scope2count=1 scope2_0_kind=Board scope2_0_value=Board commentlength=0
DiffPairsRouting Diff_100E [All] p0 off: scope1count=1 scope1_0_kind=Board scope1_0_value=Board scope2count=1 scope2_0_kind=Board scope2_0_value=Board commentlength=70 // Protel DXP Scope 1 Expression Was: InDifferentialPairClass('100E')
DiffPairsRouting Diff_90E [All] p0 off: scope1count=1 scope1_0_kind=Board scope1_0_value=Board scope2count=1 scope2_0_kind=Board scope2_0_value=Board commentlength=69 // Protel DXP Scope 1 Expression Was: InDifferentialPairClass('90E')
DiffPairsRouting Diff_100E [InDifferentialPairClass('100E')] p1: maxlimit=10 minlimit=7 mostfreqgap=10 toplayer_maxgap=7 toplayer_prefgap=7 toplayer_minwidth=4 toplayer_maxwidth=4 toplayer_prefwidth=4 midlayer1_mingap=10 midlayer1_minwidth=15 midlayer1_maxwidth=15 midlayer1_prefwidth=15 midlayer2_mingap=8 midlayer2_maxgap=8 midlayer2_prefgap=8 midlayer2_minwidth=3.5 midlayer2_maxwidth=3.5 midlayer2_prefwidth=3.5 midlayer3_mingap=10 midlayer3_minwidth=15 midlayer3_maxwidth=15 midlayer3_prefwidth=15 midlayer6_mingap=10 midlayer6_minwidth=15 midlayer6_maxwidth=15 midlayer6_prefwidth=15 midlayer7_mingap=8 midlayer7_maxgap=8 midlayer7_prefgap=8 midlayer7_minwidth=3.5 midlayer7_maxwidth=3.5 midlayer7_prefwidth=3.5 midlayer8_mingap=10 midlayer8_minwidth=15 midlayer8_maxwidth=15 midlayer8_prefwidth=15 bottomlayer_maxgap=7 bottomlayer_prefgap=7 bottomlayer_minwidth=4 bottomlayer_maxwidth=4 bottomlayer_prefwidth=4 maxuncoupledlength=500
DiffPairsRouting Diff_90E [InDifferentialPairClass('90E')] p2: maxlimit=100 minlimit=4.5 mostfreqgap=10 toplayer_maxgap=4.5 toplayer_prefgap=4.5 toplayer_minwidth=4 toplayer_maxwidth=4 toplayer_prefwidth=4 midlayer1_mingap=10 midlayer1_minwidth=15 midlayer1_maxwidth=15 midlayer1_prefwidth=15 midlayer2_mingap=6 midlayer2_maxgap=6 midlayer2_prefgap=6 midlayer2_minwidth=4 midlayer2_maxwidth=4 midlayer2_prefwidth=4 midlayer3_mingap=10 midlayer3_minwidth=15 midlayer3_maxwidth=15 midlayer3_prefwidth=15 midlayer6_mingap=10 midlayer6_minwidth=15 midlayer6_maxwidth=15 midlayer6_prefwidth=15 midlayer7_mingap=6 midlayer7_maxgap=6 midlayer7_prefgap=6 midlayer7_minwidth=4 midlayer7_maxwidth=4 midlayer7_prefwidth=4 midlayer8_mingap=10 midlayer8_minwidth=15 midlayer8_maxwidth=15 midlayer8_prefwidth=15 bottomlayer_maxgap=4.5 bottomlayer_prefgap=4.5 bottomlayer_minwidth=4 bottomlayer_maxwidth=4 bottomlayer_prefwidth=4 maxuncoupledlength=1000
DiffPairsRouting Diff_120E [All] p3: maxlimit=10 minlimit=6.1 mostfreqgap=10 toplayer_maxgap=6.1 toplayer_prefgap=6.1 toplayer_minwidth=4 toplayer_maxwidth=4 toplayer_prefwidth=4 midlayer1_mingap=10 midlayer1_minwidth=15 midlayer1_maxwidth=15 midlayer1_prefwidth=15 midlayer2_mingap=10 midlayer2_minwidth=15 midlayer2_maxwidth=15 midlayer2_prefwidth=15 midlayer3_mingap=10 midlayer3_minwidth=15 midlayer3_maxwidth=15 midlayer3_prefwidth=15 midlayer6_mingap=10 midlayer6_minwidth=15 midlayer6_maxwidth=15 midlayer6_prefwidth=15 midlayer7_mingap=10 midlayer7_minwidth=15 midlayer7_maxwidth=15 midlayer7_prefwidth=15 midlayer8_mingap=10 midlayer8_minwidth=15 midlayer8_maxwidth=15 midlayer8_prefwidth=15 bottomlayer_maxgap=6.1 bottomlayer_prefgap=6.1 bottomlayer_minwidth=4 bottomlayer_maxwidth=4 bottomlayer_prefwidth=4 maxuncoupledlength=500
FabricationTestPointUsage TestPointUsage [All] p0: scope1count=1 scope1_0_kind=Board scope1_0_value=Board scope2count=1 scope2_0_kind=Board scope2_0_value=Board commentlength=0 valid=2 allowmultiple=FALSE
FabricationTestPointUsage TestPointUsage [All] p1: valid=2 allowmultiple=FALSE
FabricationTestpoint Testpoint [All] p0: scope1count=1 scope1_0_kind=Board scope1_0_value=Board scope2count=1 scope2_0_kind=Board scope2_0_value=Board commentlength=0 side=3 testpointundercomponent=TRUE minsize=40 maxsize=100 preferedsize=60 minholesize=0 maxholesize=40 preferedholesize=32 testpointgrid=1
FabricationTestpoint Testpoint [All] p1: side=3 testpointundercomponent=TRUE minsize=40 maxsize=100 preferedsize=60 minholesize=0 maxholesize=40 preferedholesize=32 testpointgrid=1 allowsidetop=TRUE allowsidebottom=TRUE usegrid=TRUE gridtolerance=0.01
FanoutControl Fanout_Small [All] p0 off: scope1count=1 scope1_0_kind=Board scope1_0_value=Board scope2count=1 scope2_0_kind=Board scope2_0_value=Board commentlength=84 // Protel DXP Scope 1 Expression Was: (CompPinCount < 5)   Fanout_Small (Default Rule)
FanoutControl Fanout_Default [All] p0: scope1count=1 scope1_0_kind=Board scope1_0_value=Board scope2count=1 scope2_0_kind=Board scope2_0_value=Board commentlength=30 // Fanout_Default (Default Rule)
FanoutControl Fanout_SOIC [All] p0 off: scope1count=1 scope1_0_kind=Board scope1_0_value=Board scope2count=1 scope2_0_kind=Board scope2_0_value=Board commentlength=71 // Protel DXP Scope 1 Expression Was: IsSOIC   Fanout_SOIC (Default Rule)
FanoutControl Fanout_BGA [All] p0 off: scope1count=1 scope1_0_kind=Board scope1_0_value=Board scope2count=1 scope2_0_kind=Board scope2_0_value=Board commentlength=69 // Protel DXP Scope 1 Expression Was: IsBGA   Fanout_BGA (Default Rule)
FanoutControl Fanout_LCC [All] p0 off: scope1count=1 scope1_0_kind=Board scope1_0_value=Board scope2count=1 scope2_0_kind=Board scope2_0_value=Board commentlength=69 // Protel DXP Scope 1 Expression Was: IsLCC   Fanout_LCC (Default Rule)
FanoutControl Fanout_LCC [IsLCC] p1: bgadir=Out bgaviamode=Centered fanoutstyle=Auto fanoutdirection=Alternating viagrid=1 // Fanout_LCC (Default Rule)
FanoutControl Fanout_BGA [IsBGA] p2: bgadir=Out bgaviamode=Centered fanoutstyle=Auto fanoutdirection=Alternating viagrid=1 // Fanout_BGA (Default Rule)
FanoutControl Fanout_Default [All] p4: bgadir=Out bgaviamode=Centered fanoutstyle=Auto fanoutdirection=Alternating viagrid=1 // Fanout_Default (Default Rule)
FanoutControl Fanout_Small [(CompPinCount < 5)] p5: bgadir=Out bgaviamode=Centered fanoutstyle=Auto fanoutdirection=OutThenIn viagrid=1 // Fanout_Small (Default Rule)
Height [All] p0: scope1count=1 scope1_0_kind=Board scope1_0_value=Board scope2count=1 scope2_0_kind=Board scope2_0_value=Board commentlength=0
HoleSize [All] p0: scope1count=1 scope1_0_kind=Board scope1_0_value=Board scope2count=1 scope2_0_kind=Board scope2_0_value=Board commentlength=0 absolutevalues=TRUE maxlimit=251 minlimit=5.9 maxpercent=80.000 minpercent=20.000
HoleSize [All] p1: absolutevalues=TRUE maxlimit=251 minlimit=5.9 maxpercent=80.000 minpercent=20.000
HoleToHoleClearance [All] p0: scope1count=1 scope1_0_kind=Board scope1_0_value=Board scope2count=1 scope2_0_kind=Board scope2_0_value=Board commentlength=0
LayerPairs [All] p0: scope1count=1 scope1_0_kind=Board scope1_0_value=Board scope2count=1 scope2_0_kind=Board scope2_0_value=Board commentlength=0 enforce=TRUE
MatchedLengths [All] p0: scope1count=1 scope1_0_kind=NetClass scope1_0_value=LVDS_IC scope2count=1 scope2_0_kind=Board scope2_0_value=Board commentlength=0 tolerance=20 amplitude=200 gap=20 style=90-Degree
MatchedLengths AR_DMM [All] p0 off: scope1count=1 scope1_0_kind=Board scope1_0_value=Board scope2count=1 scope2_0_kind=Board scope2_0_value=Board commentlength=63 tolerance=100 amplitude=200 gap=20 style=90-Degree // Protel DXP Scope 1 Expression Was: InxSignalClass('AR_DMM')
MatchedLengths USB [All] p0 off: scope1count=1 scope1_0_kind=Board scope1_0_value=Board scope2count=1 scope2_0_kind=Board scope2_0_value=Board commentlength=60 tolerance=5 amplitude=200 gap=20 style=90-Degree // Protel DXP Scope 1 Expression Was: InxSignalClass('USB')
MatchedLengths JTAG [All] p0 off: scope1count=1 scope1_0_kind=Board scope1_0_value=Board scope2count=1 scope2_0_kind=Board scope2_0_value=Board commentlength=61 tolerance=100 amplitude=200 gap=20 style=90-Degree // Protel DXP Scope 1 Expression Was: InxSignalClass('JTAG')
MatchedLengths SPI [All] p0 off: scope1count=1 scope1_0_kind=Board scope1_0_value=Board scope2count=1 scope2_0_kind=Board scope2_0_value=Board commentlength=70 tolerance=200 amplitude=200 gap=20 style=90-Degree // Protel DXP Scope 1 Expression Was: InxSignalClass('SPI & HOSTINT')
MatchedLengths QSPI [All] p0 off: scope1count=1 scope1_0_kind=Board scope1_0_value=Board scope2count=1 scope2_0_kind=Board scope2_0_value=Board commentlength=61 tolerance=100 amplitude=200 gap=20 style=90-Degree // Protel DXP Scope 1 Expression Was: InxSignalClass('QSPI')
MatchedLengths [InNetClass('LVDS_IC')] p1: tolerance=20 checknetsindiffpair=FALSE checkdiffpairvsdiffpair=TRUE checkxsignals=TRUE checkothers=TRUE
MatchedLengths AR_DMM [InxSignalClass('AR_DMM')] p2: tolerance=100 checknetsindiffpair=FALSE checkdiffpairvsdiffpair=TRUE checkxsignals=TRUE checkothers=TRUE
MatchedLengths USB [InxSignalClass('USB')] p3: tolerance=5 checknetsindiffpair=TRUE checkdiffpairvsdiffpair=FALSE checkxsignals=FALSE checkothers=FALSE
MatchedLengths QSPI [InxSignalClass('QSPI')] p4: tolerance=100 checknetsindiffpair=FALSE checkdiffpairvsdiffpair=TRUE checkxsignals=TRUE checkothers=TRUE
MatchedLengths SPI [InxSignalClass('SPI & HOSTINT')] p5: tolerance=200 checknetsindiffpair=FALSE checkdiffpairvsdiffpair=TRUE checkxsignals=TRUE checkothers=TRUE
MatchedLengths JTAG [InxSignalClass('JTAG')] p6: tolerance=100 checknetsindiffpair=FALSE checkdiffpairvsdiffpair=TRUE checkxsignals=TRUE checkothers=TRUE
MinimumAnnularRing [All] p0: scope1count=1 scope1_0_kind=Board scope1_0_value=Board scope2count=1 scope2_0_kind=Board scope2_0_value=Board commentlength=0 minimumring=3
MinimumAnnularRing MinimumAnnularRing_ThermalPadVias [All] p0 off: scope1count=1 scope1_0_kind=Board scope1_0_value=Board scope2count=1 scope2_0_kind=Board scope2_0_value=Board commentlength=63 minimumring=3 // Protel DXP Scope 1 Expression Was: IsVia and InAnyComponent
MinimumAnnularRing MinimumAnnularRing_ThermalPadVias [IsVia and InAnyComponent] p1: minimumring=3
MinimumAnnularRing [All] p2: minimumring=3
MinimumSolderMaskSliver [All] p0: scope1count=1 scope1_0_kind=Board scope1_0_value=Board scope2count=1 scope2_0_kind=Board scope2_0_value=Board commentlength=0
MinimumSolderMaskSliver [All] p1: minsoldermaskwidth=3
NetAntennae [All] p0: scope1count=1 scope1_0_kind=Board scope1_0_value=Board scope2count=1 scope2_0_kind=Board scope2_0_value=Board commentlength=0
PasteMaskExpansion [All] p0: scope1count=1 scope1_0_kind=Board scope1_0_value=Board scope2count=1 scope2_0_kind=Board scope2_0_value=Board commentlength=0 expansion=0
PlaneClearance [All] p0: scope1count=1 scope1_0_kind=Board scope1_0_value=Board scope2count=1 scope2_0_kind=Board scope2_0_value=Board commentlength=0 clearance=20
PlaneConnect [All] p0: scope1count=1 scope1_0_kind=Board scope1_0_value=Board scope2count=1 scope2_0_kind=Board scope2_0_value=Board commentlength=0 planeconnectstyle=Direct reliefexpansion=10 reliefentries=4 reliefconductorwidth=10 reliefairgap=10
PlaneConnect [All] p1: planeconnectstyle=Direct reliefexpansion=10 reliefentries=4 reliefconductorwidth=10 reliefairgap=10
PolygonConnect [All] p0: scope1count=1 scope1_0_kind=Board scope1_0_value=Board scope2count=1 scope2_0_kind=Board scope2_0_value=Board commentlength=0 connectstyle=Direct reliefconductorwidth=10 reliefentries=4 polygonreliefangle="90 Angle"
PolygonConnect [All] p1: connectstyle=Direct reliefconductorwidth=10 reliefentries=4 polygonreliefangle="90 Angle" airgapwidth=10
RoomDefinition BGA [All] p0: scope1count=1 scope1_0_kind=ComponentClass scope1_0_value=60GHz-AOP_IR_FLASH scope2count=1 scope2_0_kind=Board scope2_0_value=Board commentlength=0 region_x1=44490000 region_y1=53680000 region_x2=50747070 region_y2=59816060 confinementstyle=ConfineIn
RoomDefinition BGA [InComponentClass('60GHz-AOP_IR_FLASH')] p1: confinementstyle=ConfineIn formatcopy=TRUE lockcomponents=FALSE outline 3757.84,4447.61 4382.71,4447.61 4382.71,3834 3757,3834
RoutingCorners [All] p0: scope1count=1 scope1_0_kind=Board scope1_0_value=Board scope2count=1 scope2_0_kind=Board scope2_0_value=Board commentlength=0 cornerstyle=45-Degree minsetback=100 maxsetback=100
RoutingLayers [All] p0: scope1count=1 scope1_0_kind=Board scope1_0_value=Board scope2count=1 scope2_0_kind=Board scope2_0_value=Board commentlength=0 top layer=Automatic mid layer 1=Automatic mid layer 2=Automatic mid layer 3=Automatic mid layer 6=Automatic mid layer 7=Automatic mid layer 8=Automatic bottom layer=Automatic
RoutingPriority [All] p0: scope1count=1 scope1_0_kind=Board scope1_0_value=Board scope2count=1 scope2_0_kind=Board scope2_0_value=Board commentlength=0
RoutingTopology [All] p0: scope1count=1 scope1_0_kind=Board scope1_0_value=Board scope2count=1 scope2_0_kind=Board scope2_0_value=Board commentlength=0 topology=Shortest
RoutingVias [All] p0: scope1count=1 scope1_0_kind=Board scope1_0_value=Board scope2count=1 scope2_0_kind=Board scope2_0_value=Board commentlength=0 holewidth=8 width=18 viastyle="Through Hole" minholewidth=7.87 minwidth=17 maxholewidth=40 maxwidth=30
RoutingVias ThermalPadVias [All] p0 off: scope1count=1 scope1_0_kind=Board scope1_0_value=Board scope2count=1 scope2_0_kind=Board scope2_0_value=Board commentlength=63 holewidth=7.87 width=19.68 viastyle="Through Hole" minholewidth=7.87 minwidth=19.68 maxholewidth=12.99 maxwidth=23.62 // Protel DXP Scope 1 Expression Was: IsVia and InAnyComponent
RoutingVias [All] p1: holewidth=8 width=18 viastyle="Through Hole" minholewidth=7.87 minwidth=17 maxholewidth=40 maxwidth=30
RoutingVias ThermalPadVias [IsVia and InAnyComponent] p2: holewidth=7.87 width=19.68 viastyle="Through Hole" minholewidth=7.87 minwidth=19.68 maxholewidth=12.99 maxwidth=23.62
ShortCircuit [All] p0: scope1count=1 scope1_0_kind=Board scope1_0_value=Board scope2count=1 scope2_0_kind=Board scope2_0_value=Board commentlength=0 allowed=FALSE
SilkToBoardRegionClearance [All] p0 off: scope1count=1 scope1_0_kind=Board scope1_0_value=Board scope2count=1 scope2_0_kind=Board scope2_0_value=Board commentlength=130 // Protel DXP Scope 1 Expression Was: Not ((IsComment or IsDesignator) And (Hide <> 'False')) and not InRegion(1000,500,4000,800)
SilkToBoardRegionClearance [Not ((IsComment or IsDesignator) And (Hide <> 'False')) and not InRegion(1000,500,4000,800)] p1:
SilkToSilkClearance [All] p0: scope1count=1 scope1_0_kind=Board scope1_0_value=Board scope2count=1 scope2_0_kind=Board scope2_0_value=Board commentlength=0
SilkToSilkClearance [All] p1: silktosilkclearance=3
SilkToSolderMaskClearance "Silk to Solder Mask Opening" [All] p0: scope1count=1 scope1_0_kind=Board scope1_0_value=Board scope2count=1 scope2_0_kind=Board scope2_0_value=Board commentlength=0
SilkToSolderMaskClearance SilkToComponentPadClearance [All] p0 off: scope1count=1 scope1_0_kind=Board scope1_0_value=Board scope2count=1 scope2_0_kind=Board scope2_0_value=Board commentlength=87 // Protel DXP Scope 1 Expression Was: (IsPad or IsFill or IsRegion) and InAnycomponent
SilkToSolderMaskClearance SilkToComponentPadClearance [(IsPad or IsFill or IsRegion) and InAnycomponent] p1: minsilkscreentomaskgap=3 clearancetoexposedcopper=TRUE
SilkToSolderMaskClearance "Silk to Solder Mask Opening" [All] p2: minsilkscreentomaskgap=3 clearancetoexposedcopper=FALSE
SolderMaskExpansion [All] p0: scope1count=1 scope1_0_kind=Board scope1_0_value=Board scope2count=1 scope2_0_kind=Board scope2_0_value=Board commentlength=0 expansion=1.97
SolderMaskExpansion [All] p1: expansion=1.97
UnRoutedNet [All] p0: scope1count=1 scope1_0_kind=Board scope1_0_value=Board scope2count=1 scope2_0_kind=Board scope2_0_value=Board commentlength=0
UnpouredPolygon [All] p0: scope1count=1 scope1_0_kind=Board scope1_0_value=Board scope2count=1 scope2_0_kind=Board scope2_0_value=Board commentlength=0
Width RF [All] p0: scope1count=1 scope1_0_kind=NetClass scope1_0_value=RF scope2count=1 scope2_0_kind=Board scope2_0_value=Board commentlength=0 maxlimit=100 minlimit=5.5 preferedwidth=10
Width [All] p0: scope1count=1 scope1_0_kind=Board scope1_0_value=Board scope2count=1 scope2_0_kind=Board scope2_0_value=Board commentlength=0 maxlimit=100 minlimit=4 preferedwidth=6
Width RF [InNetClass('RF')] p1: maxlimit=100 minlimit=5.5 preferedwidth=10 toplayer_prefwidth=12 midlayer1_minwidth=10 midlayer1_maxwidth=10 midlayer2_minwidth=10 midlayer2_maxwidth=10 midlayer3_minwidth=10 midlayer3_maxwidth=10 midlayer6_minwidth=10 midlayer6_maxwidth=10 midlayer7_minwidth=10 midlayer7_maxwidth=10 midlayer8_minwidth=10 midlayer8_maxwidth=10 bottomlayer_minwidth=10 bottomlayer_maxwidth=10 minimp=50.000000 maximp=50.000000 favimp=50.000000
Width [All] p2: maxlimit=100 minlimit=4 preferedwidth=6 toplayer_maxwidth=40 toplayer_prefwidth=5.5 midlayer1_minwidth=4.2 midlayer1_maxwidth=20 midlayer1_prefwidth=4.2 midlayer2_minwidth=4.2 midlayer2_maxwidth=20 midlayer2_prefwidth=4.2 midlayer7_minwidth=4.2 midlayer7_maxwidth=20 midlayer7_prefwidth=4.2 midlayer8_minwidth=6 midlayer8_prefwidth=10 bottomlayer_maxwidth=40 bottomlayer_prefwidth=5.5 minimp=50.000000 maximp=50.000000 favimp=50.000000
15 further rules are at their usual default settings.

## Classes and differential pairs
net class LVDS_CONN: NetJ2_28 NetJ2_30 NetJ2_34 NetJ2_36 NetJ2_40 NetJ2_42 NetJ2_46 NetJ2_48
net class LVDS_IC: AR_LVDS_0_N AR_LVDS_0_P AR_LVDS_1_N AR_LVDS_1_P AR_LVDS_CLK_N AR_LVDS_CLK_P AR_LVDS_FRCLK_N AR_LVDS_FRCLK_P
net class RF: NetA1_4 NetC21_2 NetC22_1 NetC41_1 NetC93_1 NetC93_2 RF_N RF_P
component class PROC091F_RST_GPIOs_I2C: C6 C9 C10 C11 C12 C13 C38 C39 C72 C120 C125 J3 LD2 LD3 LD5 Q1 R13 R18 R38 R42 R51 R57 R67 R68 R69 R70 R71 R72 R73 R77 R78 R80 R81 R82 R93 R96 R97 R98 R107 R108 R111 R124 R125 R129 R177 R178 SW2 SW3 TP15 TP20 U5 U6 U7 U16 Y4
component class PROC091F_PMIC: C30 C31 C32 C33 C34 C44 C45 C46 C47 C48 C49 C50 C51 C52 C53 C54 C77 FL1 FL8 FL9 FL10 FL20 L2 L3 L4 L5 L11 L12 L13 L14 LD1 R25 R26 R28 R31 R32 R33 R34 R35 R36 R37 R39 R50 R52 R53 R54 R55 R56 TP5 TP12 U1
component class PROC091F_HD_CONN_PWR_SW: C127 C128 C129 D2 FL11 FL22 J2 R10 R11 R12 R14 R20 R24 R27 R29 R58 R88 R92 R130 R132 R133 R135 R137 R138 R140 RA1 RA2 RA3 RA4 RA5 RA6 RA7 RA8 RA9 TP10 TP13 U19
component class PROC091F_FLASH_USB_TO_UART: C1 C2 C3 C4 C100 C101 C126 D1 FL2 J1 LD4 R6 R15 R19 R40 R41 R43 R44 R45 R46 R47 R48 R49 R60 R61 R62 R63 R64 R65 TP18 TP19 TP26 U3 U9 U18
component class PROC091F_CAN_INTERFACE: C40 C43 C105 C106 C107 C108 C109 C110 FL3 FL12 J8 J10 R66 R74 R104 R105 R106 R114 R115 R116 R117 R118 R119 R120 R121 R122 R123 R126 R127 R128 R134 R136 R139 R141 U11 U12 U13 U17
component class PROC091F_BT_DISPLAY: A1 C5 C7 C8 C15 C16 C17 C18 C19 C20 C21 C22 C23 C24 C25 C26 C27 C28 C29 C35 C36 C37 C41 C86 C93 C99 C104 C114 C115 C116 C117 C118 C119 J4 J6 J7 L1 L6 L7 L8 L9 L10 LD6 R17 R30 R76 R79 R86 R87 R89 R90 R91 R94 R95 R99 R100 R101 R102 R110 R112 R113 R131 R160 R161 R166 R168 R180 R181 R182 R183 R184 R185 TP16 TP27 TP46 U4 U8 U10 U14 Y2 Y3
component class PROC091F_AOP_PWR: C55 C56 C57 C58 C59 C60 C61 C62 C63 C64 C65 C66 C67 C68 C69 C70 C73 C74 C75 C76 C78 C79 C80 C81 C82 C83 C84 C85 C87 C88 C89 C90 C91 C92 C94 C95 C96 C97 C98 C102 C103 FL6 FL7 TP11
component class PROC091F_AOP_IO: C14 C71 C130 J9 R2 R3 R4 R5 R7 R8 R9 R21 R22 R23 R59 R75 R83 R84 R85 R103 R109 R158 R159 R170 R171 R172 R174 R176 S3 TP2 TP3 TP6 TP7 TP8 TP9 TP14 TP17 U2 Y1
component class PROC091F_ANALOG_MUX: C42 C122 C123 FL14 J5 R1 R16 S1 S2 TP4 U15
component class PROC091F_Hardware: FID1 FID2 FID3 FID4 FID5 FID6 ZZ1 ZZ2 ZZ3 ZZ4 ZZ5.1 ZZ5.2
component class FiducialMark: FID1 FID2 FID3 FID4 FID5 FID6
component class AssemblyNote: ZZ1 ZZ2 ZZ3 ZZ4 ZZ5.1 ZZ5.2
differential pair CAN2: +NetJ10_1 -NetJ10_3
differential pair NewDifferentialPair1: +NetR41_1 -NetR60_1
differential pair USB: +USB_DM -USB_DP
differential pair CAN: +NetJ8_1 -NetJ8_3
differential pair X48M: +X48M_N -X48M_P
differential pair AR_XTAL: +AR_XTAL_N -AR_XTAL_P
differential pair AR_LVDS_FRCLK: +AR_LVDS_FRCLK_N -AR_LVDS_FRCLK_P
differential pair AR_LVDS_CLK: +AR_LVDS_CLK_N -AR_LVDS_CLK_P
differential pair AR_LVDS_1: +AR_LVDS_1_N -AR_LVDS_1_P
differential pair " ": +AR_LVDS_0_N -AR_LVDS_0_P

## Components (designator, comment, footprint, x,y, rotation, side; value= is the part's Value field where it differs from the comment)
A1 "ANT016008LCS2442MA2" FP-ANT016008LCS2442MA2_SMT_ANT-0 6517.1,4550.46 r180 top
C1 "CL05A106MP5NUNC" 0402_070 3245.8,4221.22 r90 top
C2 "GRM033R6YA104KE14D" "FP-GRM033R6YA104KE14D_0201 (0603 Metric)-IPC_C" 3785.88,4170.74 r90 bottom
C3 "GRM033R6YA104KE14D" "FP-GRM033R6YA104KE14D_0201 (0603 Metric)-IPC_C" 3772.95,4125.72 r180 bottom
C4 "CL05A106MP5NUNC" 0402_070 3226.3,4334.4 r90 bottom
C5 "CL03A105MO3NRNH" FP-CL03A105MO3NRNH_0201-IPC_C 6371,3977 r180 bottom
C6 "GRM033R6YA104KE14D" "FP-GRM033R6YA104KE14D_0201 (0603 Metric)-IPC_C" 5221.01,4103.02 r0 bottom locked
C7 "CL05A106MP5NUNC" 0402_070 6332.97,3720.79 r0 bottom
C8 "CL03A103KA3NNNC" FP-CL03A103KA3NNNC_0201-IPC_C 6391.38,3719.01 r180 bottom
C9 "GRM033R6YA104KE14D" "FP-GRM033R6YA104KE14D_0201 (0603 Metric)-IPC_C" 5197.1,3791.56 r90 bottom locked
C10 "GRM033R6YA104KE14D" "FP-GRM033R6YA104KE14D_0201 (0603 Metric)-IPC_C" 5157.67,3880.39 r90 bottom locked
C11 "CL03A105MO3NRNH" FP-CL03A105MO3NRNH_0201-IPC_C 5160.25,3791.5 r270 bottom locked
C12 "GRM033R6YA104KE14D" "FP-GRM033R6YA104KE14D_0201 (0603 Metric)-IPC_C" 5598.06,3727.05 r90 bottom
C13 "GRM033R6YA104KE14D" "FP-GRM033R6YA104KE14D_0201 (0603 Metric)-IPC_C" 5227.18,4028.9 r0 bottom
C14 "GRM0335C1H4R7BA01D" 0201_033L 3719.34,4001.36 r90 top
C15 "CL03A105MO3NRNH" FP-CL03A105MO3NRNH_0201-IPC_C 4785.89,4131.62 r270 top locked
C16 "CL03A105MO3NRNH" FP-CL03A105MO3NRNH_0201-IPC_C 4753.82,4132.42 r270 top locked
C17 "GRM0335C1H8R0BA01D" "FP-GRM0335C1H8R0BA01D_0201 (0603 metric)-IPC_C" 6038.8,4212.94 r90 top
C18 "GRM0335C1H8R0BA01D" "FP-GRM0335C1H8R0BA01D_0201 (0603 metric)-IPC_C" 6038.8,4166.75 r270 top
C19 "250R05L120JV4T" FP-250R05L120JV4T_0201-IPC_C 5765.79,4370.87 r270 top
C20 "250R05L120JV4T" FP-250R05L120JV4T_0201-IPC_C 5765.79,4324.98 r90 top
C21 "CL05C120JB5NNNC" 0402L 6028.92,4344.09 r270 top
C22 "GCM1555C1H1R0CA16D" 0402L 5956.7,4395.47 r270 top
C23 "GCM1555C1H1R0CA16D" 0402L 5883.59,4324.42 r180 top
C24 "CL03A105MO3NRNH" FP-CL03A105MO3NRNH_0201-IPC_C 5630.51,4003.46 r180 top
C25 "GRM033R6YA104KE14D" "FP-GRM033R6YA104KE14D_0201 (0603 Metric)-IPC_C" 5629.37,4224.38 r180 top
C26 "GRM033R6YA104KE14D" "FP-GRM033R6YA104KE14D_0201 (0603 Metric)-IPC_C" 5630.37,4042.21 r180 top
C27 "GRM033R6YA104KE14D" "FP-GRM033R6YA104KE14D_0201 (0603 Metric)-IPC_C" 6047.37,4128.46 r0 top
C28 "CL05A226MQ5N6J8" FP-CL05A226MQ5N6J8_0402-IPC_C 5984.12,3931.35 r270 top
C29 "CL05A226MQ5N6J8" FP-CL05A226MQ5N6J8_0402-IPC_C 5958.37,4142.46 r180 bottom
C30 "LMK063BJ224MP-F" 0201_033L 3304,4158.52 r90 top
C31 "TMK063CG391JT-F" "FP-TMK063CG391JT-F_0201 (0603 Metric)-IPC_C" 3562.13,4311.22 r90 top
C32 "TMK063CG391JT-F" "FP-TMK063CG391JT-F_0201 (0603 Metric)-IPC_C" 3268.13,4312.11 r90 top
C33 "TMK063CG391JT-F" "FP-TMK063CG391JT-F_0201 (0603 Metric)-IPC_C" 3559.04,4025.1 r90 top
C34 "TMK063CG391JT-F" "FP-TMK063CG391JT-F_0201 (0603 Metric)-IPC_C" 3277.23,4022.75 r90 top
C35 "GRM033R6YA104KE14D" "FP-GRM033R6YA104KE14D_0201 (0603 Metric)-IPC_C" 5959.54,4181.25 r180 bottom
C36 "GRM033R6YA104KE14D" "FP-GRM033R6YA104KE14D_0201 (0603 Metric)-IPC_C" 6006.44,4219.38 r0 top
C37 "GRM033R6YA104KE14D" "FP-GRM033R6YA104KE14D_0201 (0603 Metric)-IPC_C" 5775.38,4411.08 r180 top
C38 "250R05L120JV4T" FP-250R05L120JV4T_0201-IPC_C 5240.41,3795.13 r180 bottom locked
C39 "250R05L120JV4T" FP-250R05L120JV4T_0201-IPC_C 5286.16,3795.3 r0 bottom locked
C40 "GRM033R6YA104KE14D" "FP-GRM033R6YA104KE14D_0201 (0603 Metric)-IPC_C" 4970.37,3934.38 r0 top locked
C41 "GCM1555C1H1R0CA16D" 0402L 5975.28,4530.78 r270 top
C42 "CL05A106MP5NUNC" 0402_070 6310,4040 r90 top
C43 "GRM033R6YA104KE14D" "FP-GRM033R6YA104KE14D_0201 (0603 Metric)-IPC_C" 5497.81,4202.58 r90 bottom
C44 "CL05A226MQ5N6J8" FP-CL05A226MQ5N6J8_0402-IPC_C 3430.22,4377.73 r270 top
C45 "CL05A226MQ5N6J8" FP-CL05A226MQ5N6J8_0402-IPC_C 3396.5,4377.26 r270 top
C46 "CL05A226MQ5N6J8" FP-CL05A226MQ5N6J8_0402-IPC_C 3429.83,3925.6 r90 top
C47 "CL05A226MQ5N6J8" FP-CL05A226MQ5N6J8_0402-IPC_C 3395.41,3925.76 r90 top
C48 "CL05A226MQ5N6J8" FP-CL05A226MQ5N6J8_0402-IPC_C 3836.23,4067.82 r180 bottom
C49 "CL05A226MQ5N6J8" FP-CL05A226MQ5N6J8_0402-IPC_C 4217.54,4191.28 r270 bottom
C50 "CL05A106MP5NUNC" 0402_070 3448.11,4283.77 r180 top
C51 "CL05A106MP5NUNC" 0402_070 3385.11,4283.77 r0 top
C52 "CL05A106MP5NUNC" 0402_070 3385.11,4033.27 r0 top
C53 "CL05A106MP5NUNC" 0402_070 3448.11,4033.27 r180 top
C54 "CL05A226MQ5N6J8" FP-CL05A226MQ5N6J8_0402-IPC_C 4185.58,4190.34 r270 bottom
C55 "CL05A106MP5NUNC" 0402_070 4115.16,4356.5 r90 bottom
C56 "LMK063BJ224MP-F" 0201_033L 4166.37,4378.24 r0 bottom
C57 "LMK063BJ224MP-F" 0201_033L 4168.42,4409.4 r0 bottom
C58 "LMK063BJ224MP-F" 0201_033L 4125.06,4410.16 r180 bottom
C59 "CL05A106MP5NUNC" 0402_070 4128.3,3985.94 r0 bottom
C60 "LMK063BJ224MP-F" 0201_033L 4378.33,3871.66 r270 top
C61 "LMK063BJ224MP-F" 0201_033L 4270.98,4185.3 r180 bottom
C62 "CL05A106MP5NUNC" 0402_070 3907,4128 r0 bottom
C63 "LMK063BJ224MP-F" 0201_033L 3737.19,4226.49 r90 top
C64 "LMK063BJ224MP-F" 0201_033L 3907,4159 r0 bottom
C65 "CL05A106MP5NUNC" 0402_070 3911,4188 r0 bottom
C66 "LMK063BJ224MP-F" 0201_033L 3908.02,4218 r0 bottom
C67 "LMK063BJ224MP-F" 0201_033L 3848,4327 r90 bottom
C68 "LMK063BJ224MP-F" 0201_033L 3884.37,4409.24 r0 bottom
C69 "GRM033R61C473KE84D" 0201_033L 3734.67,4322.98 r270 top
C70 "CL05A106MP5NUNC" 0402_070 3891,4337 r180 bottom
C71 "GRM0335C1H4R7BA01D" 0201_033L 3722.86,4065.25 r270 top
C72 "GRM033R6YA104KE14D" "FP-GRM033R6YA104KE14D_0201 (0603 Metric)-IPC_C" 4853.37,4217.48 r270 top
C73 "CL05A106MP5NUNC" 0402_070 3897,4303 r180 bottom
C74 "CL03A225MQ3CRNC" 0201L 3945.46,4346.38 r180 bottom
C75 "LMK063BJ224MP-F" 0201_033L 3945.46,4409.24 r180 bottom
C76 "LMK063BJ224MP-F" 0201_033L 3945.46,4377.91 r180 bottom
C77 "CL05A226MQ5N6J8" FP-CL05A226MQ5N6J8_0402-IPC_C 3415.03,4422.66 r0 top
C78 "CL05A106MP5NUNC" 0402_070 4038.9,4317.13 r180 bottom
C79 "CL03A225MQ3CRNC" 0201L 4071.88,4346.34 r0 bottom
C80 "LMK063BJ224MP-F" 0201_033L 4073.37,4377.75 r0 bottom
C81 "LMK063BJ224MP-F" 0201_033L 4071.88,4409.36 r0 bottom
C82 "CL05A106MP5NUNC" 0402_070 4001.02,4277.32 r0 bottom
C83 "CL03A225MQ3CRNC" 0201L 4008.9,4346.15 r0 bottom
C84 "LMK063BJ224MP-F" 0201_033L 4009.24,4377.83 r0 bottom
C85 "LMK063BJ224MP-F" 0201_033L 4009.24,4409.33 r0 bottom
C86 "GRM033R6YA104KE14D" "FP-GRM033R6YA104KE14D_0201 (0603 Metric)-IPC_C" 5910.41,3935.32 r0 bottom
C87 "LMK063BJ224MP-F" 0201_033L 4025.62,3891.02 r0 bottom
C88 "LMK063BJ224MP-F" 0201_033L 4394.91,4124.76 r0 top
C89 "CGB2A1X6S0J105K033BC" 0402L 3717.5,4135.45 r180 top
C90 "CGB2A1X6S0J105K033BC" 0402L 3717.37,4182.85 r180 top
C91 "GRM033R6YA104KE14D" "FP-GRM033R6YA104KE14D_0201 (0603 Metric)-IPC_C" 4292.99,4035.17 r180 bottom
C92 "GRM033R6YA104KE14D" "FP-GRM033R6YA104KE14D_0201 (0603 Metric)-IPC_C" 4065.74,3883.1 r90 bottom
C93 "CL05C120JB5NNNC" 0402L 6205.98,4550.46 r180 top
C94 "LMK063BJ224MP-F" 0201_033L 4293.19,3964.68 r180 bottom
C95 "LMK063BJ224MP-F" 0201_033L 3922.37,3891.76 r90 bottom
C96 "LMK063BJ224MP-F" 0201_033L 4388.37,4235.76 r90 top
C97 "LMK063BJ224MP-F" 0201_033L 3779.79,4050.2 r90 bottom
C98 "LMK063BJ224MP-F" 0201_033L 4388.37,4297.76 r270 top
C99 "GJM1555C1H1R8BB01D" 0402L 6328.98,4550.46 r180 top
C100 "CL03A105MO3NRNH" FP-CL03A105MO3NRNH_0201-IPC_C 3741.24,3861.69 r0 bottom
C101 "GRM033R6YA104KE14D" "FP-GRM033R6YA104KE14D_0201 (0603 Metric)-IPC_C" 3741,3881.17 r0 bottom
C102 "CL03A225MQ3CRNC" 0201L 4393.22,4090.26 r0 top
C103 "CL03A225MQ3CRNC" 0201L 4291.98,4058.8 r180 bottom
C104 "GJM1555C1H1R8BB01D" 0402L 6450.41,4530.78 r270 top
C105 "GRM033R6YA104KE14D" "FP-GRM033R6YA104KE14D_0201 (0603 Metric)-IPC_C" 5402.37,4347.37 r90 bottom
C106 "GRM155R71H472KA01D" 0402L 5574,4430.51 r270 bottom
C107 "GRM033R6YA104KE14D" "FP-GRM033R6YA104KE14D_0201 (0603 Metric)-IPC_C" 6223.22,4433.22 r90 top
C108 "GRM033R6YA104KE14D" "FP-GRM033R6YA104KE14D_0201 (0603 Metric)-IPC_C" 6197.97,3866.01 r270 top
C109 "GRM033R6YA104KE14D" "FP-GRM033R6YA104KE14D_0201 (0603 Metric)-IPC_C" 6365.6,3768.9 r0 top
C110 "GRM155R71H472KA01D" 0402L 6440,3773.61 r90 top
C114 "GRM033R6YA104KE14D" "FP-GRM033R6YA104KE14D_0201 (0603 Metric)-IPC_C" 5662.76,3747.34 r180 bottom
C115 "CL03A105MO3NRNH" FP-CL03A105MO3NRNH_0201-IPC_C 5685.98,3907.2 r0 top
C116 "CL03A105MO3NRNH" FP-CL03A105MO3NRNH_0201-IPC_C 5686.69,3878.74 r0 top
C117 "GRM033R6YA104KE14D" "FP-GRM033R6YA104KE14D_0201 (0603 Metric)-IPC_C" 5334.39,4536.81 r0 bottom locked
C118 "GRM033R6YA104KE14D" "FP-GRM033R6YA104KE14D_0201 (0603 Metric)-IPC_C" 5760.69,3733.87 r270 bottom
C119 "GRM033R6YA104KE14D" "FP-GRM033R6YA104KE14D_0201 (0603 Metric)-IPC_C" 5797.1,3909.21 r90 bottom
C120 "GRM033R6YA104KE14D" "FP-GRM033R6YA104KE14D_0201 (0603 Metric)-IPC_C" 4784.37,4437.46 r90 top
C122 "CL05A106MP5NUNC" 0402_070 6260,4040 r270 top
C123 "GRM033R6YA104KE14D" "FP-GRM033R6YA104KE14D_0201 (0603 Metric)-IPC_C" 5489.38,3956.46 r180 bottom
C125 "CL03A103KA3NNNC" FP-CL03A103KA3NNNC_0201-IPC_C 5270.83,4102.9 r0 bottom locked
C126 "GRM033R6YA104KE14D" "FP-GRM033R6YA104KE14D_0201 (0603 Metric)-IPC_C" 3679.93,4262.91 r0 top
C127 "GRM033R6YA104KE14D" "FP-GRM033R6YA104KE14D_0201 (0603 Metric)-IPC_C" 6141.37,3936.75 r180 bottom
C128 "GRM033R6YA104KE14D" "FP-GRM033R6YA104KE14D_0201 (0603 Metric)-IPC_C" 6131.47,3761.12 r180 bottom
C129 "CL03A105MO3NRNH" FP-CL03A105MO3NRNH_0201-IPC_C 6207.77,3815.74 r270 bottom
C130 "GRM033R6YA104KE14D" "FP-GRM033R6YA104KE14D_0201 (0603 Metric)-IPC_C" 4251.69,4228 r180 bottom
D1 "NSR20F30NXT5G" DSN2_0603 3229.54,4211.99 r270 bottom
D2 "NSR20F30NXT5G" DSN2_0603 4603.84,3756.88 r0 top locked
Designator1 "Comment" MHNP_M2_PANHEAD_PHILLIPS 3109.58,4791.47 r0 top
Designator1_1 "BRAKE_WAY_HOLES1X2" BRAKE_WAY_HOLES1X2 3221.89,3788.2 r180 bottom
Designator2 "BRAKE_WAY_HOLES1X2" BRAKE_WAY_HOLES1X2 3778.11,4495.01 r180 top
Designator2_1 "BRAKE_WAY_HOLES1X2" BRAKE_WAY_HOLES1X2 3778.11,3788.2 r180 bottom
Designator3 "BRAKE_WAY_HOLES1X2" BRAKE_WAY_HOLES1X2 4273.11,4495.01 r180 top
Designator3_1 "BRAKE_WAY_HOLES1X2" BRAKE_WAY_HOLES1X2 4273.11,3788.2 r180 bottom
Designator4 "BRAKE_WAY_HOLES1X2" BRAKE_WAY_HOLES1X2 4688.11,4648.59 r180 top
Designator4_1 "BRAKE_WAY_HOLES1X2" BRAKE_WAY_HOLES1X2 4688.11,3650.25 r180 bottom
Designator5 "BRAKE_WAY_HOLES1X2" BRAKE_WAY_HOLES1X2 6176.11,4648.39 r180 top
Designator5_1 "BRAKE_WAY_HOLES1X2" BRAKE_WAY_HOLES1X2 6176.11,3650.45 r180 bottom
Designator5_2 "BRAKE_WAY_HOLES1X2" BRAKE_WAY_HOLES1X2 5433.11,3650.05 r180 bottom
Designator6 "Comment" MHNP_M2_PANHEAD_PHILLIPS 6500.3,4791.47 r0 top
Designator7 "Comment" MHNP_M2_PANHEAD_PHILLIPS 3109.58,3507.37 r0 top
Designator8 "Comment" MHNP_M2_PANHEAD_PHILLIPS 6500.3,3507.37 r0 top
Designator10 "BRAKE_WAY_HOLES1X2" BRAKE_WAY_HOLES1X2 3221.89,4495.01 r180 top
Designator22_1 "Comment" MHNP_2-5 5908.96,3794.29 r0 bottom
Designator23 "Comment" MHNP_2-5 5014.62,3794.28 r0 bottom locked
FID1 "Fiducial" FIDUCIAL6.4-20 3259.58,3507.37 r0 top
FID2 "Fiducial" FIDUCIAL6.4-20 3259.58,4791.47 r0 top
FID3 "Fiducial" FIDUCIAL6.4-20 6350.3,3507.37 r0 top
FID4 "Fiducial" FIDUCIAL6.4-20 6350.3,3507.37 r180 bottom
FID5 "Fiducial" FIDUCIAL6.4-20 3259.58,4791.47 r180 bottom
FID6 "Fiducial" FIDUCIAL6.4-20 3259.58,3507.37 r180 bottom
FL1 "BLM15PD300SZ1D" 0402L 3949.54,4288.55 r90 bottom
FL2 "BLM15PD300SZ1D" 0402L 3228.8,4133.28 r90 bottom
FL3 "BLM15PD300SZ1D" 0402L 6159,3836 r270 top
FL6 "BLM15PD300SZ1D" 0402L 3153.46,4388.19 r180 top
FL7 "BLM15PD300SZ1D" 0402L 3835,4188.31 r90 bottom
FL8 "BLM15PD300SZ1D" 0402L 4170.37,4339.04 r180 bottom
FL9 "BLM15PD300SZ1D" 0402L 3881.31,4271 r180 bottom
FL10 "BLM15PD300SZ1D" 0402L 3978.37,3984.87 r0 bottom
FL11 "BLM15PD300SZ1D" 0402L 4674.94,3755.5 r180 top locked
FL12 "BLM15PD300SZ1D" 0402L 5450.1,4210.46 r180 bottom
FL14 "BLM15PD300SZ1D" 0402L 6330,4105.18 r180 top
FL20 "BLM15PD300SZ1D" 0402L 3552.13,4385.05 r180 top
FL22 "BLM15PD300SZ1D" 0402L 4843.47,3842.73 r270 top locked
J1 "105017-0001" CONN_105017-0001 3119.51,4164.78 r90 bottom
J2 "QSH-030-01-L-D-A" Samtec_QSH-030-01-X-D-A 4733.36,4144.5 r0 bottom locked
J3 "M50-3930442" FP-M50-3930442_HDR4-RECOMMENDED_LAND_PATTERN 5065.29,4581.75 r0 bottom
J4 "51441-1093" FP-51441-1093_CONN_SMD_FFC-0 4585.45,4173.34 r270 top locked
J5 "105017-0001" CONN_105017-0001 6486.85,4155.73 r90 top
J6 "51441-1093" FP-51441-1093_CONN_SMD_FFC-0 5633.17,3775.17 r0 top
J7 "GRPB052MWCN-RC" FP-GRPB052MWCN-RC_HDR10-MFG 5736.47,4571.46 r0 bottom
J8 "M50-3930342" FP-M50-3930342_HDR3-MFG 5459.37,4574.83 r0 bottom
J9 "U.FL-R-SMT-1(01)" CONN_UFL-R-SMT-1 5232.96,4283.6 r90 top
J10 "M50-3930342" FP-M50-3930342_HDR3-MFG 6582.37,3800 r90 top
L1 "LQG15HS2N4S02D" IND_LQG15H 5975.41,4324.41 r0 top
L2 "MCKK2012TR47M" "FP-MCKK2012TR47M_0805 (2012 Metric)-IPC_C" 3480.98,4358.44 r270 top
L3 "MCKK2012TR47M" "FP-MCKK2012TR47M_0805 (2012 Metric)-IPC_C" 3346.24,4358.44 r270 top
L4 "MCKK2012TR47M" "FP-MCKK2012TR47M_0805 (2012 Metric)-IPC_C" 3480.98,3957.6 r90 top
L5 "MCKK2012TR47M" "FP-MCKK2012TR47M_0805 (2012 Metric)-IPC_C" 3344.24,3957.6 r90 top
L6 "LQG15HS2N4S02D" IND_LQG15H 5903.37,4396.46 r90 top
L7 "MLZ2012N6R8LT000" 0805_HV 5980.15,4040.83 r90 bottom
L8 "BLM18HE152SN1D" 0603L 6040.76,3919.1 r90 top
L9 "LQG15HS2N0S02D" IND_LQG15H 5930.04,4485.35 r90 top
L10 "LQG15HS2N0S02D" IND_LQG15H 6085.98,4550.46 r0 top
L11 "BLM18SG260TN1D" 0603L 3892.39,4015.02 r0 bottom
L12 "BLM18SG260TN1D" 0603L 4090.19,4281.1 r180 bottom
L13 "BLM18SG260TN1D" 0603L 3242.64,4385.23 r180 top
L14 "BLM18SG260TN1D" 0603L 4121.43,4229.06 r180 bottom
LD1 "APHHS1005CGCK" APHHS1005_Green 3121.65,4188.5 r0 top
LD2 "APHHS1005CGCK" APHHS1005_Green 4607.12,4561.07 r180 top locked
